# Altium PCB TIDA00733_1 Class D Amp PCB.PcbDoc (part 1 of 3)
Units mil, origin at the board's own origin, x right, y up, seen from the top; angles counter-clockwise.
Board outline 5700 x 4500 mil, 4 copper layers (Top Layer, Signal Layer 1, Signal Layer 2, Bottom Layer), stack 61.668 mil thick; 305 components, 186 nets, 894 pads, 1056 vias.
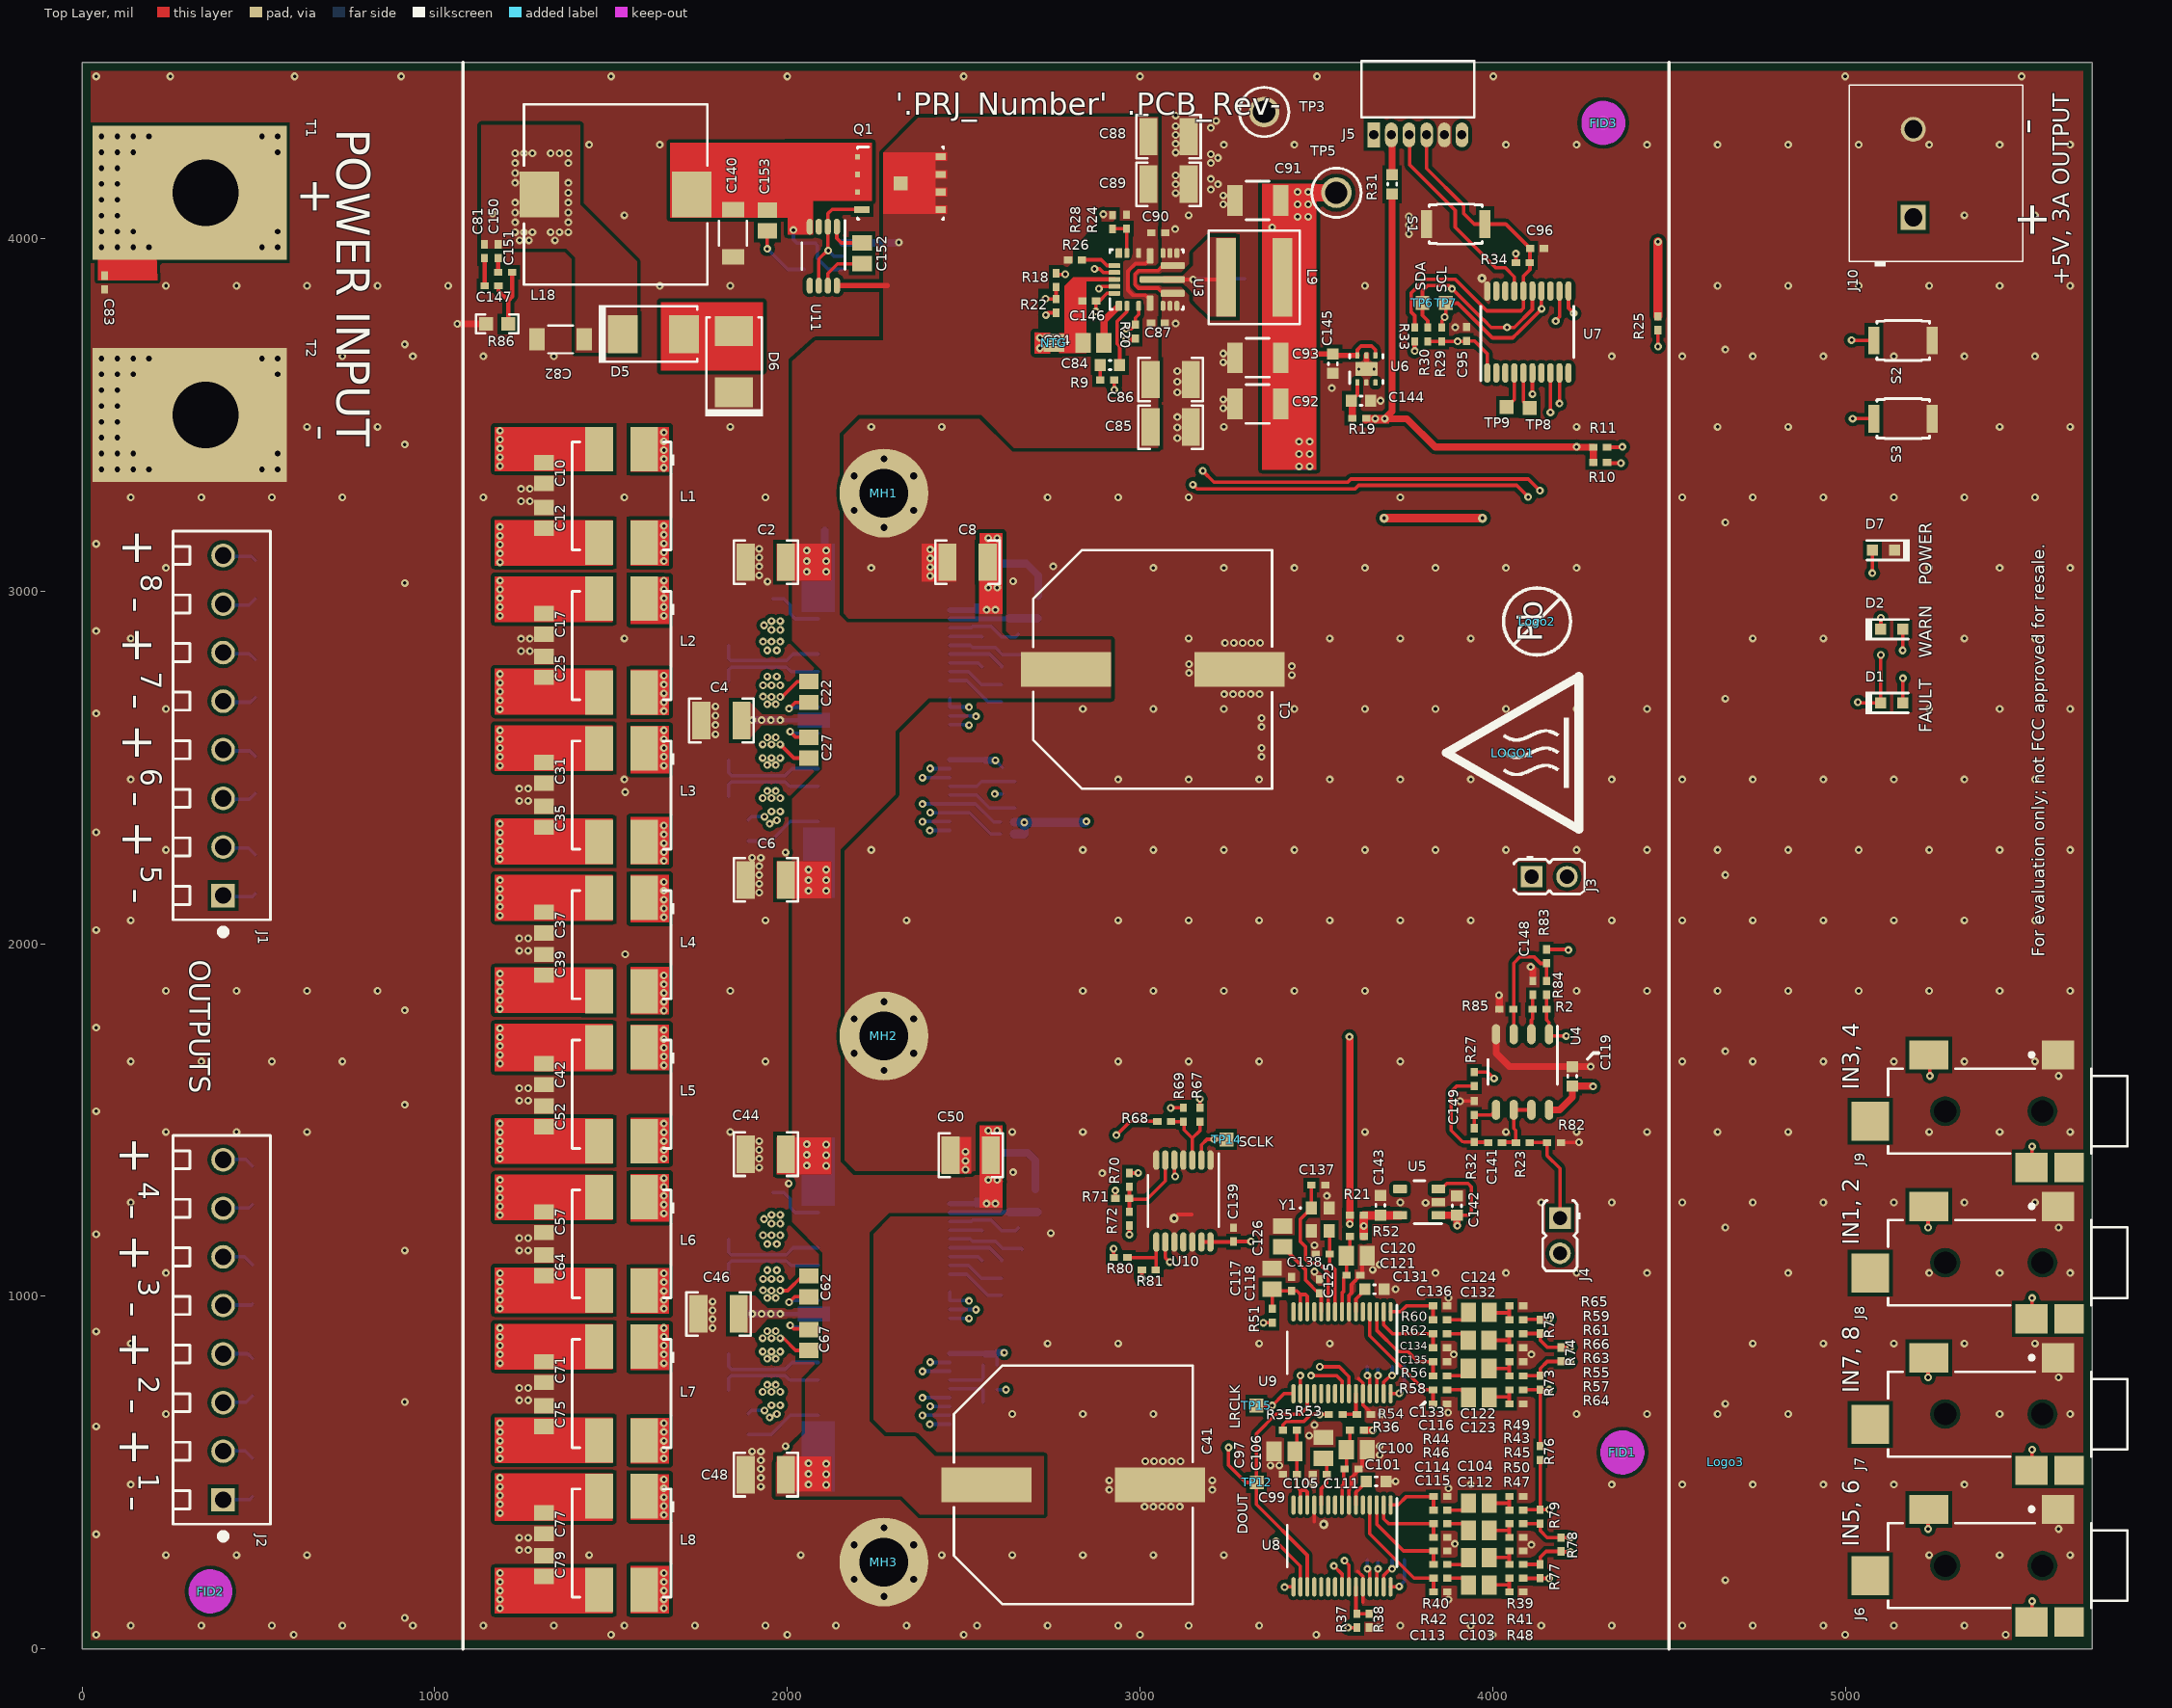
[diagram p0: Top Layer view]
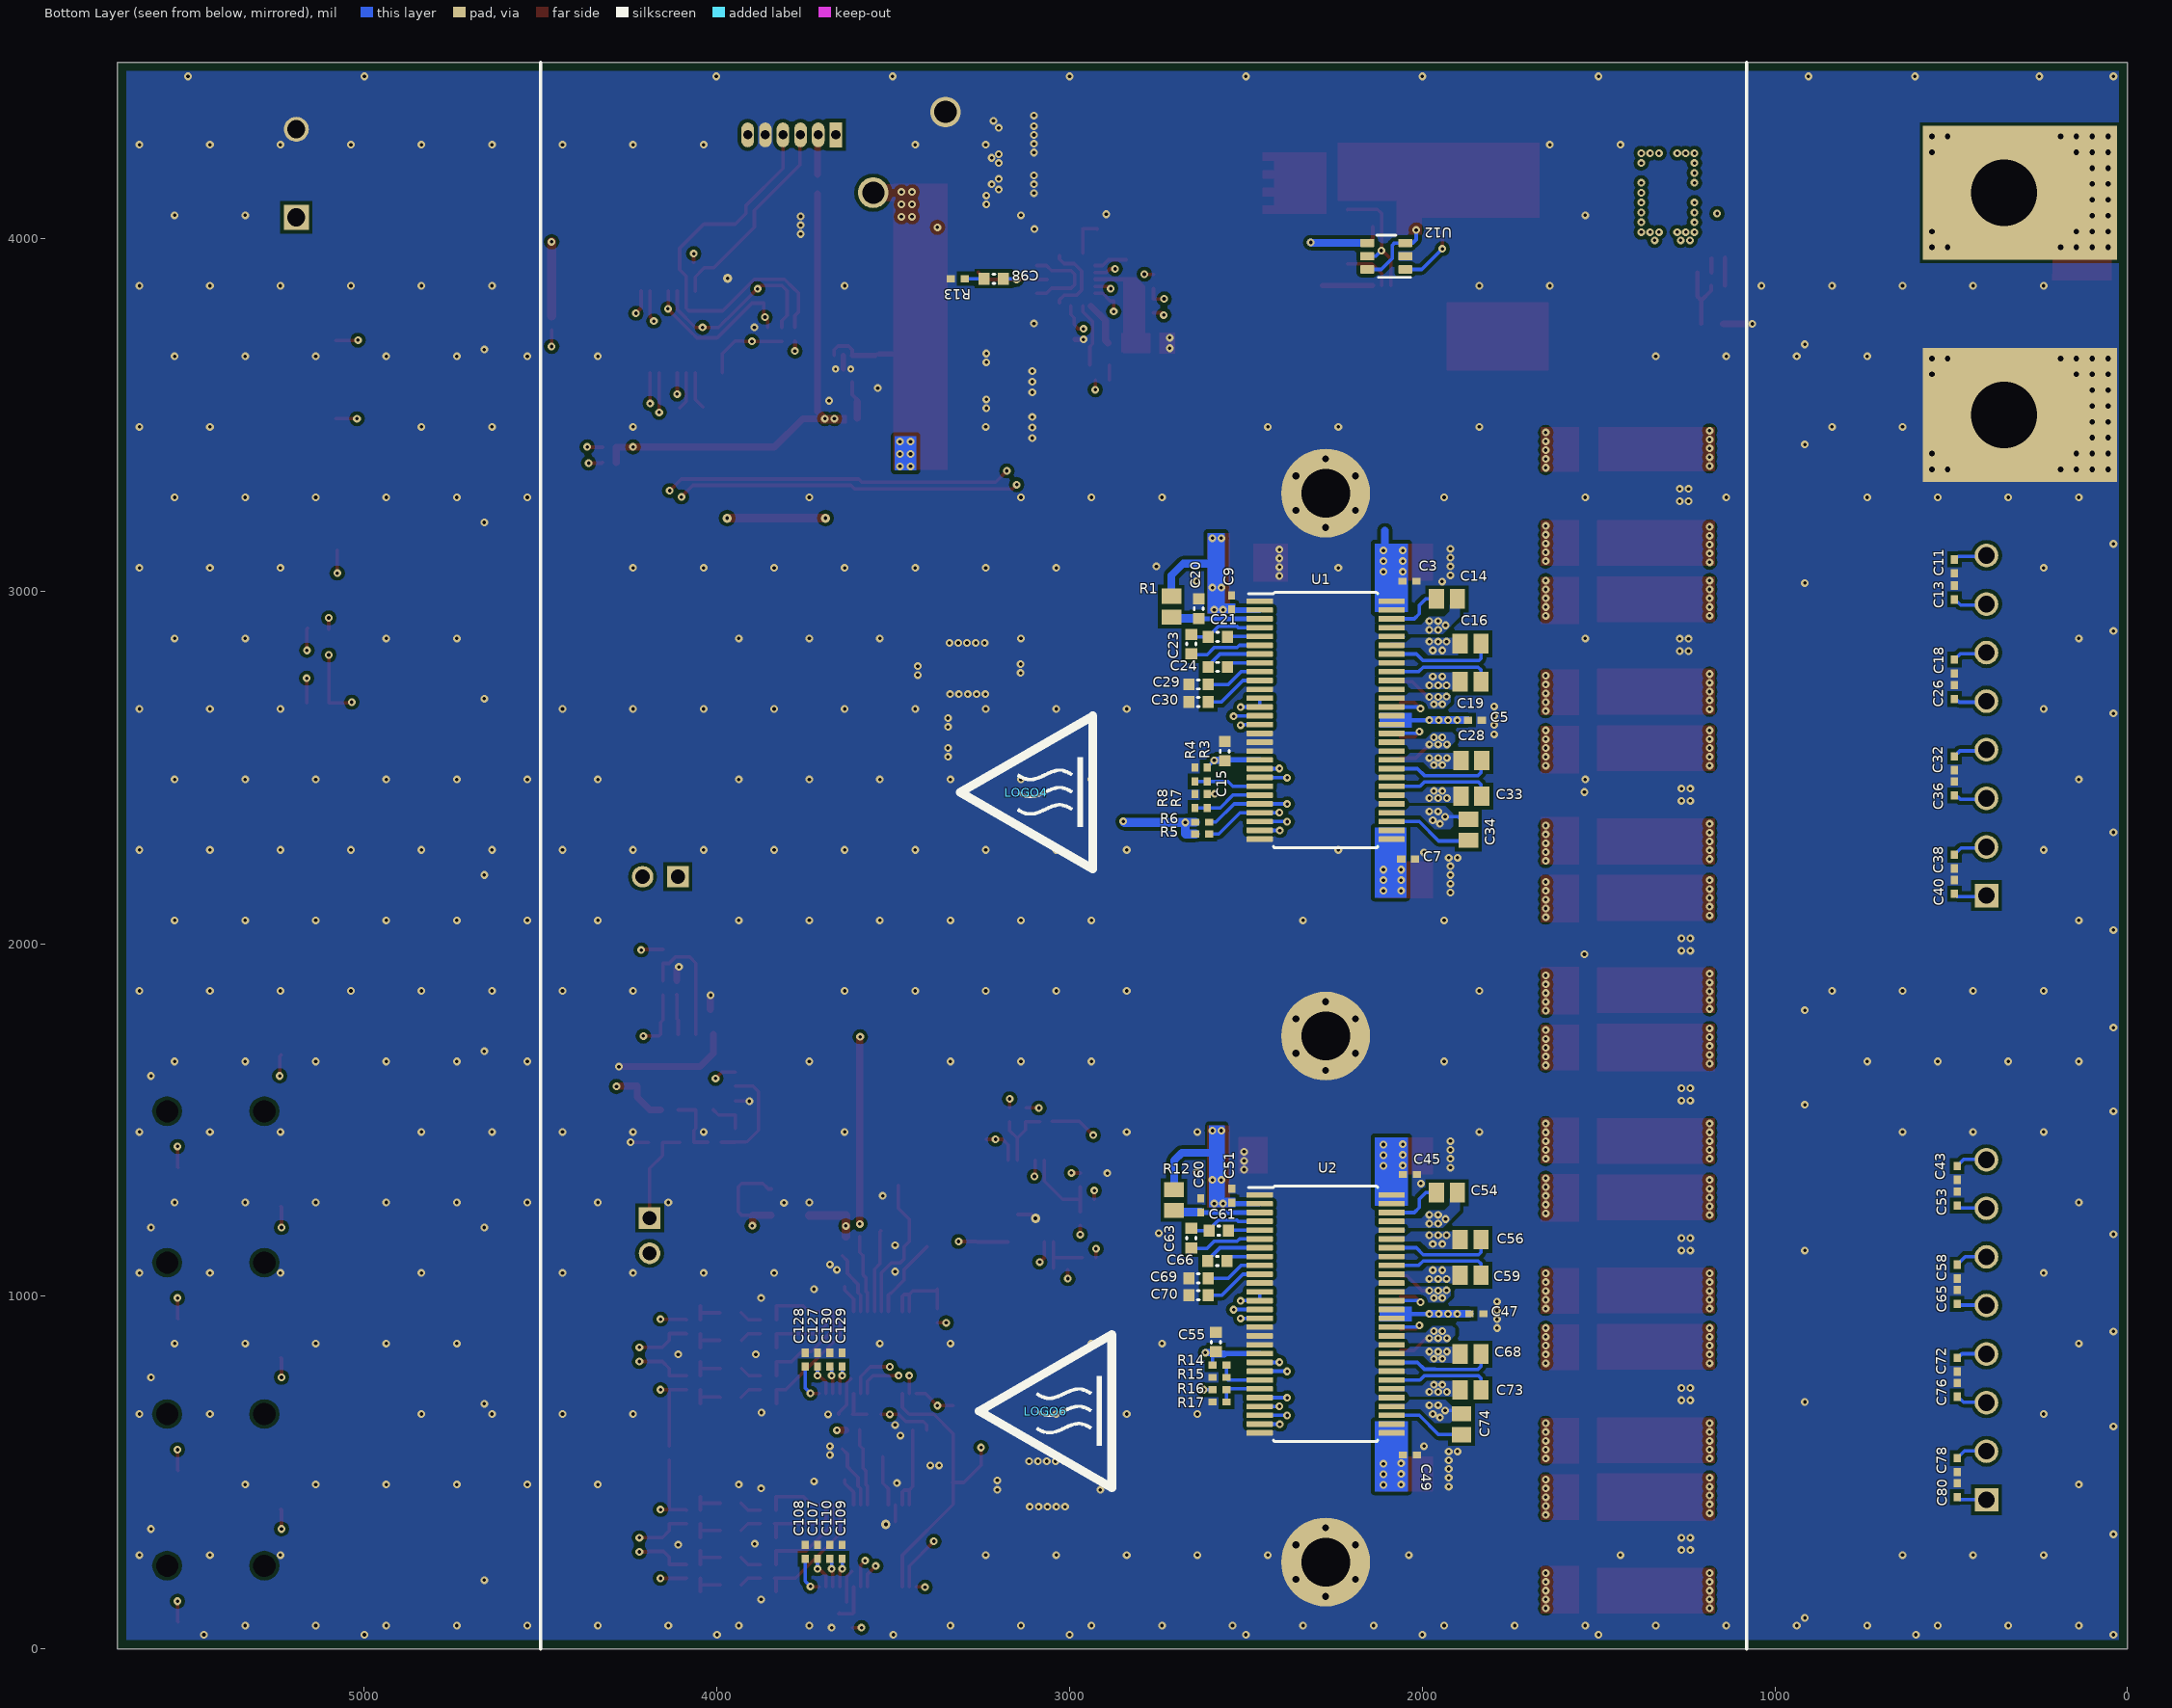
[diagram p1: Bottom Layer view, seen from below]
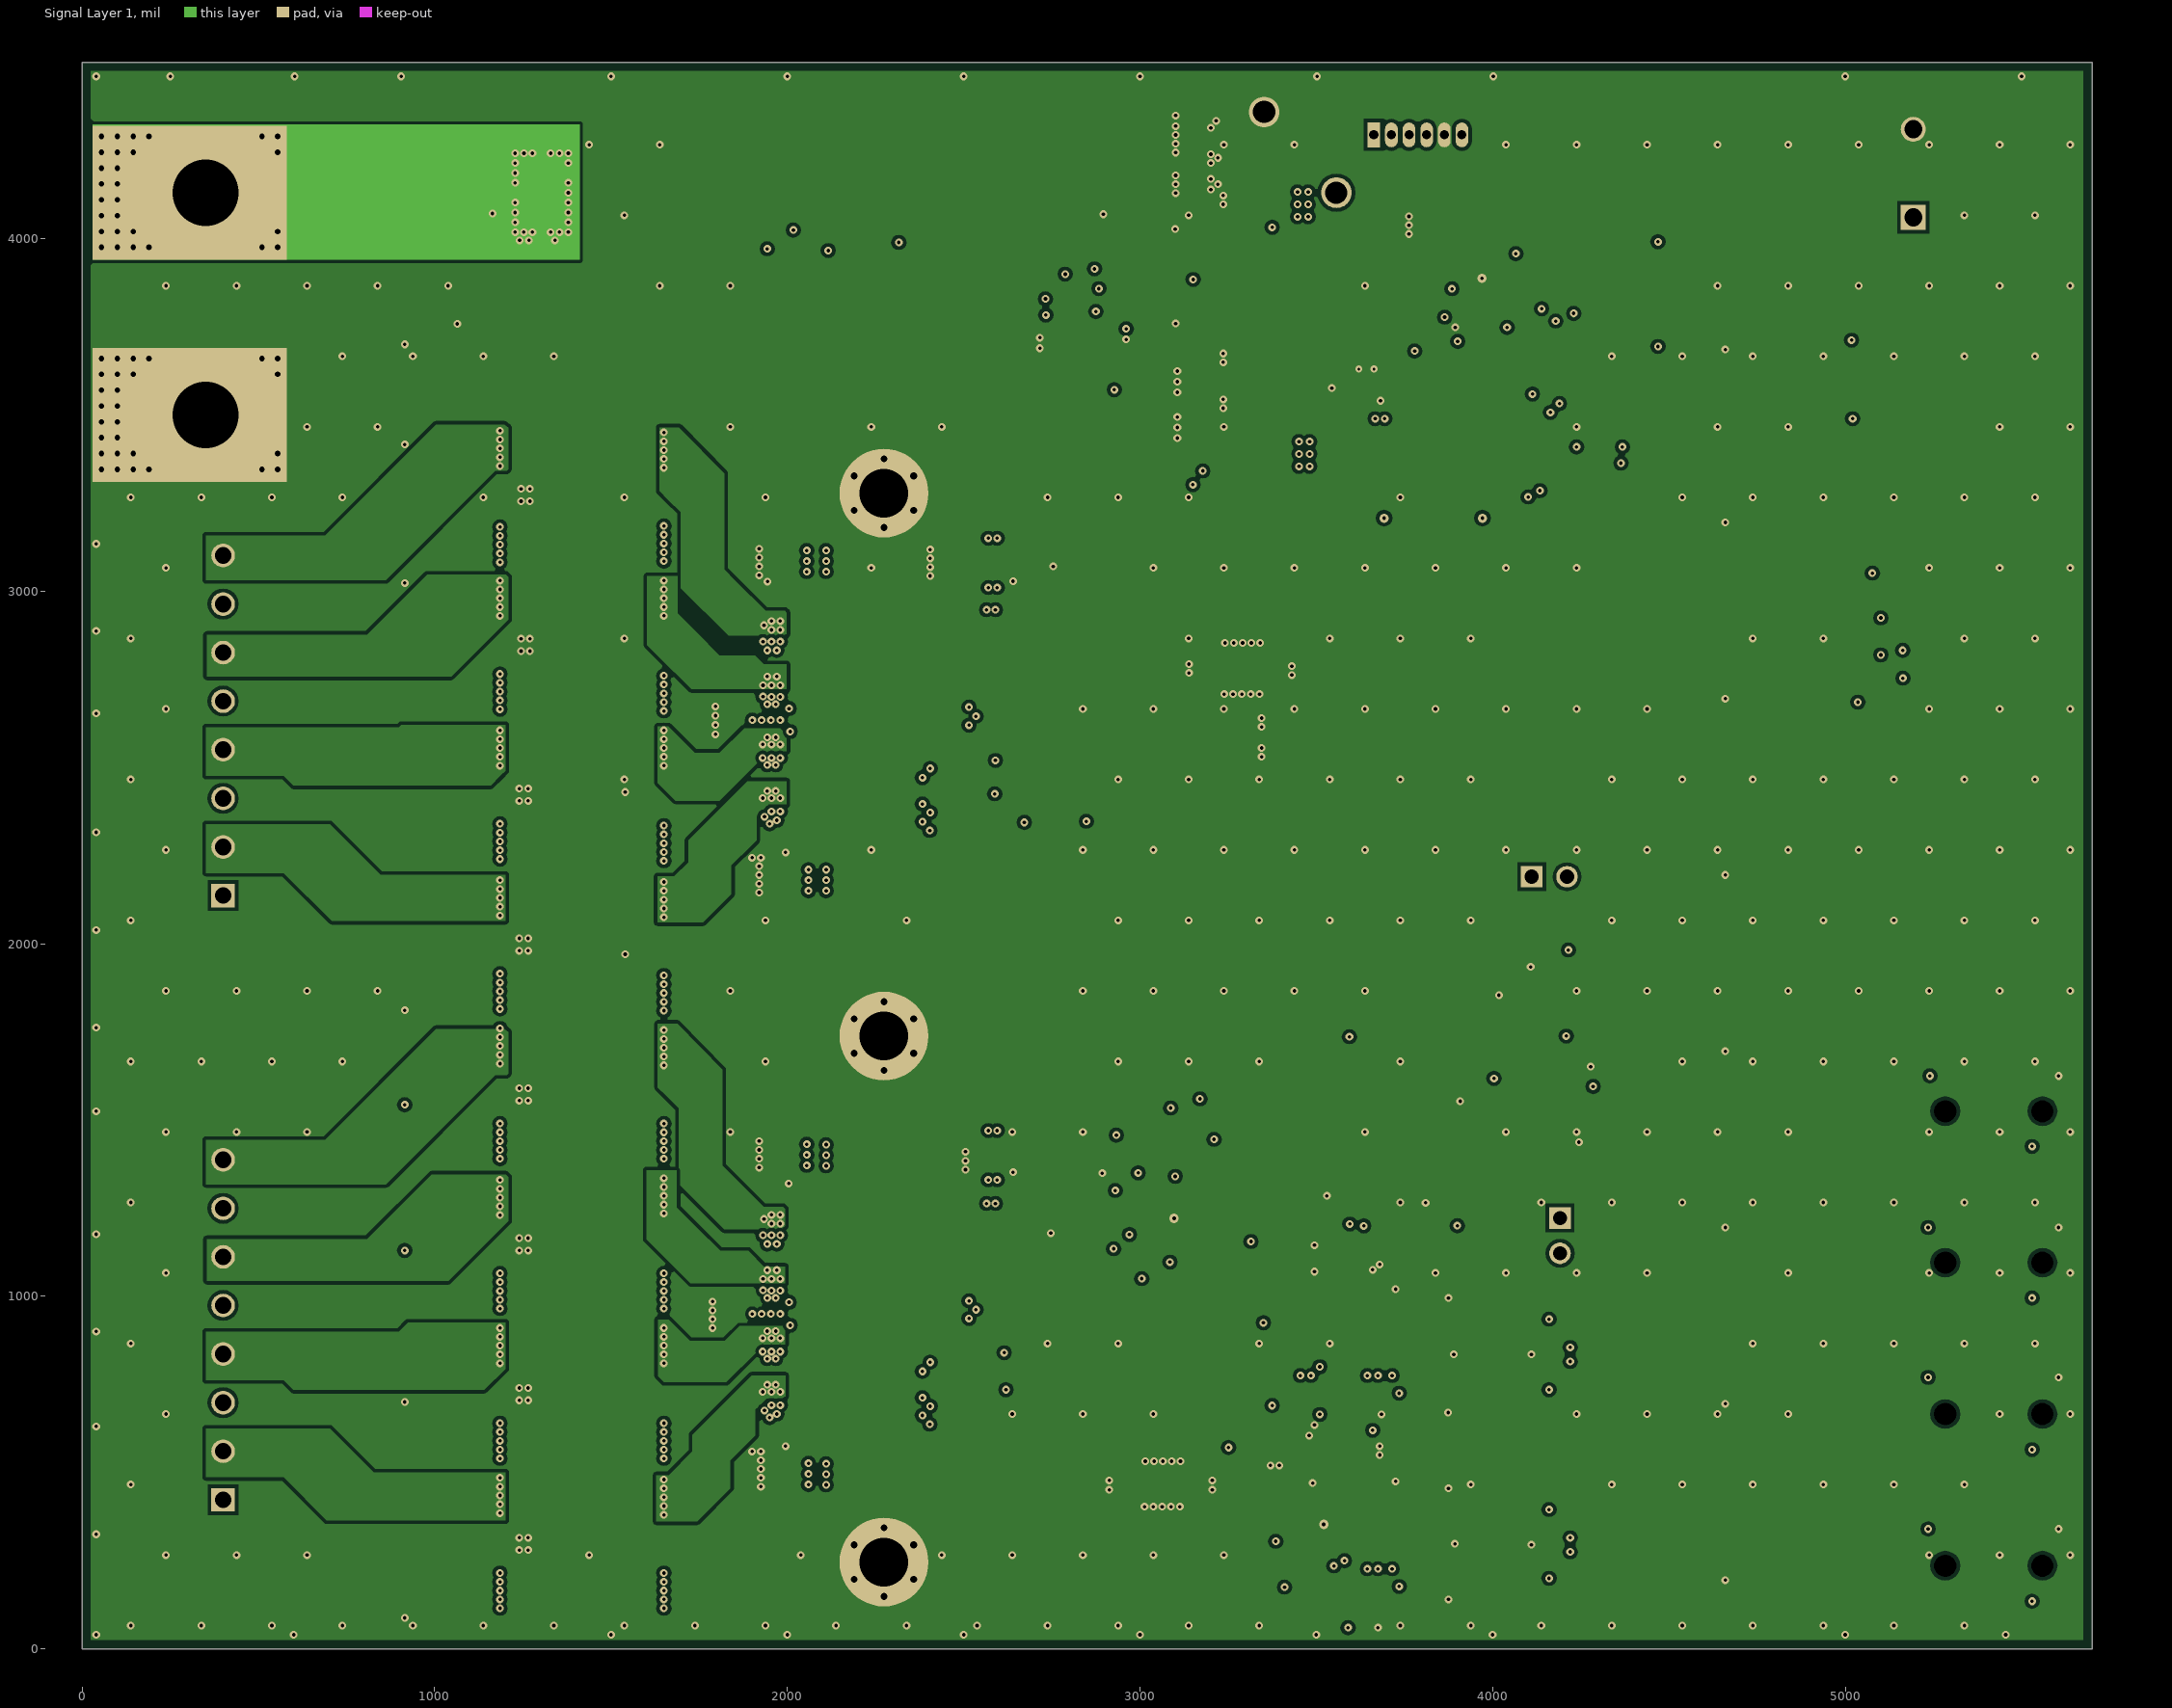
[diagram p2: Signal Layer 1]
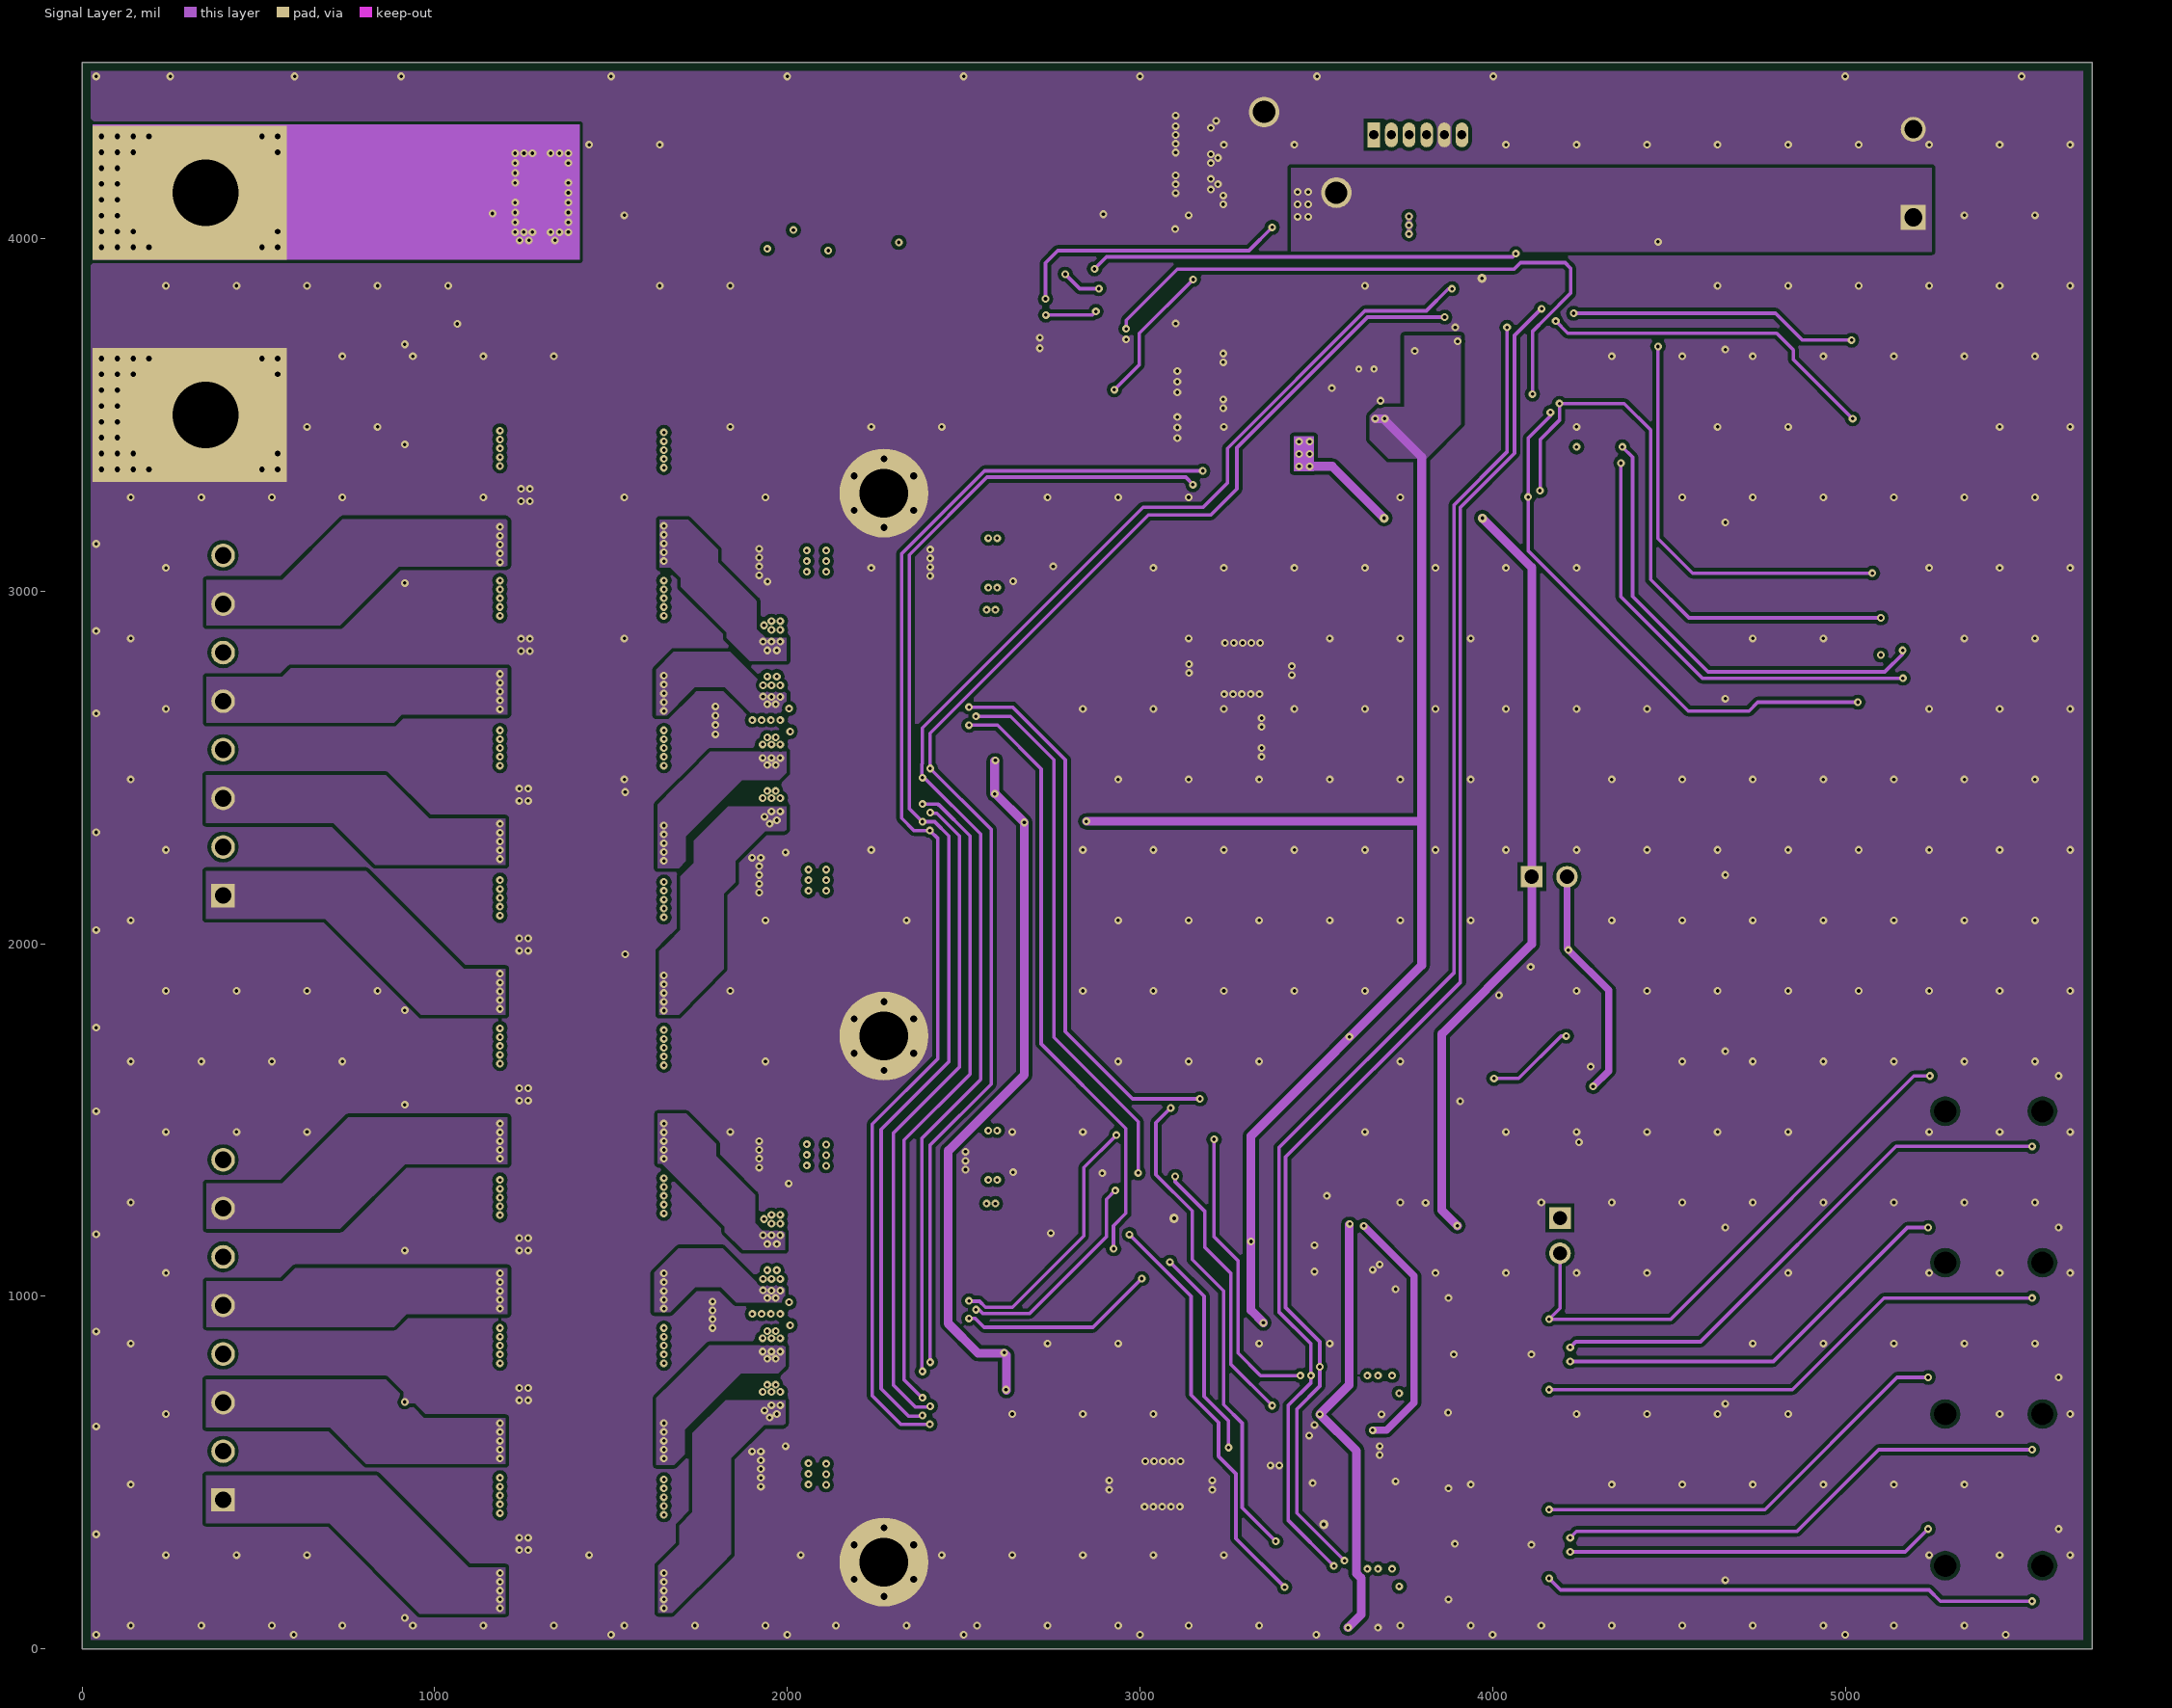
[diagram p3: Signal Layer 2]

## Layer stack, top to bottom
Top Solder: solder mask 0.4, Solder Resist, Dk 3.5
Top Layer: signal copper 1.417
Dielectric1: core 10, FR-4 High TG, Dk 4.3
Signal Layer 1: signal copper 1.417
Dielectric 2: prepreg 36, FR-4 High TG, Dk 4.2
Signal Layer 2: signal copper 1.417
Dielectric 3: core 10, FR-4 High TG, Dk 4.2
Bottom Layer: signal copper 1.417
Bottom Solder: solder mask 0.4, Solder Resist, Dk 3.5

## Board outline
0,0 0,4500 5700,4500 5700,0

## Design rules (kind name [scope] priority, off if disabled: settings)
AcuteAngle [All] p1: minimum=4.50000000000000E+0001 checktracksonly=FALSE
AssemblyTestPointUsage [All] p1: valid=2
BoardOutlineClearance BoardOutlineClearance_MountingHoles [OnCopper and InComponentClass('Mounting Holes')] p1: gap=40 ignorepadtopadclearanceinfootprint=FALSE
BoardOutlineClearance BoardOutlineClearance_Poly [OnCopper and InPoly] p2: gap=25 ignorepadtopadclearanceinfootprint=FALSE
BoardOutlineClearance [OnCopper and Not InComponentClass('Logo') and not InComponentClass('FiducialMark') and not InRegion(1000,500,4000,800)] p3: gap=25 ignorepadtopadclearanceinfootprint=FALSE
Clearance Clearance_1 [HasFootprint('RNL0022A_NV')] p1: gap=5.9 ignorepadtopadclearanceinfootprint=FALSE except(0: Arc-Hole Track-Hole SMDPad-Hole THPad-Hole Via-Hole Fill-Hole Poly-Hole Region-Hole Text-Hole)
Clearance Clearance_Keepouts [((IsTrack Or IsArc) And Not InPoly) And IsFree and IsKeepOut vs ((IsTrack Or IsArc) And Not InPoly) And IsFree and IsKeepOut] p2: gap=0 ignorepadtopadclearanceinfootprint=FALSE
Clearance Clearance_Poly [InPolygon] p3: gap=10 ignorepadtopadclearanceinfootprint=FALSE except(0: Arc-Hole Track-Hole SMDPad-Hole THPad-Hole Via-Hole Fill-Hole Poly-Hole Region-Hole Text-Hole)
Clearance [All] p4: gap=7.8 ignorepadtopadclearanceinfootprint=FALSE except(0: Arc-Hole Track-Hole SMDPad-Hole THPad-Hole Via-Hole Fill-Hole Poly-Hole Region-Hole Text-Hole)
ComponentClearance ComponentClearance_1 [HasGenericStepModel] p1: gap=0 collisioncheckmode=3 verticalgap=0 showdistances=FALSE
ComponentClearance ComponentClearance_MountingHoles_FiducialMarks [InComponentClass('Mounting Holes') vs InComponentClass('FiducialMark')] p2: gap=50 collisioncheckmode=3 verticalgap=10 showdistances=FALSE
ComponentClearance ComponentClearance_Shunt [InComponentClass('Header') vs InComponentClass('Shunt')] p3: gap=0 collisioncheckmode=3 verticalgap=0 showdistances=FALSE
ComponentClearance ComponentClearance_Logo [InComponentClass('Logo')] p4: gap=50 collisioncheckmode=3 verticalgap=10 showdistances=FALSE
ComponentClearance ComponentClearance_ScrewToNut [(HasFootprint('NY PMS 440 0025 PH')) vs (HasFootprint('Keystone_1902C'))] p5: gap=5 collisioncheckmode=3 verticalgap=10 showdistances=FALSE
ComponentClearance ComponentClearance_MountingHoles [InComponentClass('Mounting Holes')] p6: gap=250 collisioncheckmode=3 verticalgap=100000 showdistances=FALSE
ComponentClearance ComponentClearance_SmallPassives [HasFootprint('0201*') or HasFootprint('0402*') or HasFootprint('0508') or HasFootprint('0603*') or HasFootprint('0612') or HasFootprint('0805*') or HasFootprint('0815*') or HasFootprint('0830*') or HasFootprint('1206*') or HasFootprint('1210*') or HasFootprint('1808*') or HasFootprint('1812*') or HasFootprint('1825*') or HasFootprint('2010*') or HasFootprint('2220*') or HasFootprint('2225*') or HasFootprint('2512*') or HasFootprint('2728*') or HasFootprint('3518*') vs HasFootprint('0201*') or HasFootprint('0402*') or HasFootprint('0508') or HasFootprint('0603*') or HasFootprint('0612') or HasFootprint('0805*') or HasFootprint('0815*') or HasFootprint('0830*') or HasFootprint('1206*') or HasFootprint('1210*') or HasFootprint('1808*') or HasFootprint('1812*') or HasFootprint('1825*') or HasFootprint('2010*') or HasFootprint('2220*') or HasFootprint('2225*') or HasFootprint('2512*') or HasFootprint('2728*') or HasFootprint('3518*')] p7: gap=10 collisioncheckmode=3 verticalgap=10 showdistances=FALSE
ComponentClearance ComponentClearance_THtoSMT [IsThruComponent vs IsSMTComponent] p8: gap=30 collisioncheckmode=3 verticalgap=30 showdistances=FALSE
ComponentClearance ComponentClearance_THtoTH [IsThruComponent vs IsThruComponent] p9: gap=20 collisioncheckmode=3 verticalgap=20 showdistances=FALSE
ComponentClearance [All] p10: gap=20 collisioncheckmode=3 verticalgap=10 showdistances=FALSE
DiffPairsRouting [All] p1: maxlimit=100 minlimit=10 mostfreqgap=10 toplayer_minwidth=15 toplayer_maxwidth=15 toplayer_prefwidth=15 midlayer1_minwidth=15 midlayer1_maxwidth=15 midlayer1_prefwidth=15 midlayer2_minwidth=15 midlayer2_maxwidth=15 midlayer2_prefwidth=15 bottomlayer_minwidth=15 bottomlayer_maxwidth=15 bottomlayer_prefwidth=15 maxuncoupledlength=1000
FabricationTestPointUsage TestPointUsage [All] p1: valid=2 allowmultiple=FALSE
FabricationTestpoint Testpoint [All] p1: side=3 testpointundercomponent=TRUE minsize=40 maxsize=100 preferedsize=60 minholesize=0 maxholesize=40 preferedholesize=32 testpointgrid=1 allowsidetop=TRUE allowsidebottom=TRUE usegrid=TRUE gridtolerance=0.01
FanoutControl Fanout_LCC [IsLCC] p1: bgadir=Out bgaviamode=Centered fanoutstyle=Auto fanoutdirection=Alternating viagrid=1 // Fanout_LCC (Default Rule)
FanoutControl Fanout_BGA [IsBGA] p2: bgadir=Out bgaviamode=Centered fanoutstyle=Auto fanoutdirection=Alternating viagrid=1 // Fanout_BGA (Default Rule)
FanoutControl Fanout_Default [All] p4: bgadir=Out bgaviamode=Centered fanoutstyle=Auto fanoutdirection=Alternating viagrid=1 // Fanout_Default (Default Rule)
FanoutControl Fanout_Small [(CompPinCount < 5)] p5: bgadir=Out bgaviamode=Centered fanoutstyle=Auto fanoutdirection=OutThenIn viagrid=1 // Fanout_Small (Default Rule)
HoleSize [All] p1: absolutevalues=TRUE maxlimit=251 minlimit=7.87 maxpercent=80.000 minpercent=20.000
MinimumAnnularRing MinimumAnnularRing_1 [InComponent('J5')] p1: minimumring=4.99
MinimumAnnularRing MinimumAnnularRing_ThermalPadVias [IsVia and InAnyComponent] p2: minimumring=5.91
MinimumAnnularRing [All] p3: minimumring=6
MinimumSolderMaskSliver MinimumSolderMaskSliver_Logo [InComponentClass('Logo') vs InComponentClass('Logo')] p1: minsoldermaskwidth=0.7
MinimumSolderMaskSliver [All] p2: minsoldermaskwidth=3.94
PlaneConnect [All] p1: planeconnectstyle=Relief reliefexpansion=10 reliefentries=4 reliefconductorwidth=10 reliefairgap=10
PolygonConnect [All] p1: connectstyle=Direct reliefconductorwidth=10 reliefentries=4 polygonreliefangle="90 Angle" airgapwidth=10
RoutingVias ThermalPadVias [IsVia and InAnyComponent] p1: holewidth=7.87 width=19.68 viastyle="Through Hole" minholewidth=7.87 minwidth=19.68 maxholewidth=20 maxwidth=40
RoutingVias [All] p2: holewidth=10 width=26 viastyle="Through Hole" minholewidth=7.87 minwidth=22 maxholewidth=40 maxwidth=65
SilkToBoardRegionClearance [Not ((IsComment or IsDesignator) And (Hide <> 'False')) and not InRegion(1000,500,4000,800)] p1:
SilkToSilkClearance SilkToSilkClearance_Pb-FreeLogo [(HasFootprint('Pb-Free_Overlay_Medium') OR HasFootprint('Pb-Free_Overlay_Small')) vs (HasFootprint('Pb-Free_Overlay_Medium') OR HasFootprint('Pb-Free_Overlay_Small'))] p1: silktosilkclearance=0
SilkToSilkClearance [All] p2: silktosilkclearance=4
SilkToSolderMaskClearance SilkToComponentPadClearance [IsPad and InAnycomponent] p1: minsilkscreentomaskgap=5 clearancetoexposedcopper=TRUE
SilkToSolderMaskClearance "Silk to Solder Mask Opening" [All] p2: minsilkscreentomaskgap=4 clearancetoexposedcopper=FALSE
SolderMaskExpansion [All] p1: expansion=1.97
Width [All] p1: maxlimit=100 minlimit=7.8 preferedwidth=10 checkconnectedcopper=TRUE
15 further rules are at their usual default settings.

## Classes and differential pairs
component class Shunt: SH-J1 SH-J2
component class Header: J3 J4
component class FiducialMark: FID1 FID2 FID3
component class AssemblyNote: ZZ1
component class "TIDA00733_1 Class D Amp Sheet 6": C117 C118 C120 C121 C122 C123 C124 C125 C126 C127 C128 C129 C130 C131 C132 C133 C134 C135 C136 C137 C138 C139 J8 J9 R51 R52 R53 R54 R55 R56 R57 R58 R59 R60 R61 R62 R63 R64 R65 R66 R67 R68 R69 R70 R71 R72 R80 R81 TP12 TP14 TP15 U9 U10 Y1

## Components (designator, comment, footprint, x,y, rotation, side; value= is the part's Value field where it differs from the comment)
C1 "EEV-FK1H102M" SM_RADIAL_J16 3036,2778 r0 top value=1000uF
C2 "GRM32ER71H106KA12L" 1210_270 1939,3082 r180 top value=10uF
C3 "C1005X7R1H104K050BB" 0402L 2036,3028 r180 bottom value=0.1uF
C4 "GRM32ER71H106KA12L" 1210_270 1813,2633 r180 top value=10uF
C5 "C1005X7R1H104K050BB" 0402L 1851,2634 r180 bottom value=0.1uF
C6 "GRM32ER71H106KA12L" 1210_270 1939,2181 r180 top value=10uF
C7 "C1005X7R1H104K050BB" 0402L 2040,2240 r180 bottom value=0.1uF
C8 "GRM32ER71H106KA12L" 1210_270 2511,3082 r180 top value=10uF
C9 "C1005X7R1H104K050BB" 0402L 2541,2968 r90 bottom value=0.1uF
C10 "GRM21BR71H105KA12L" 0805L#1 1310,3335 r270 top value=1uF
C11 "GCM155R71H103KA55D" 0402L 491,3070 r270 bottom value=0.01uF
C12 "GRM21BR71H105KA12L" 0805L#1 1310,3208 r90 top value=1uF
C13 "GCM155R71H103KA55D" 0402L 491,2996 r90 bottom value=0.01uF
C14 "C2012X7R1H225K125AC" 0805L#1 1930,2978 r0 bottom value=2.2uF
C15 "C1608X7R1E105K080AB" 0603L 2560,2546 r90 bottom value=1uF
C16 "C2012X7R1H225K125AC" 0805L#1 1863,2851 r180 bottom value=2.2uF
C17 "GRM21BR71H105KA12L" 0805L#1 1310,2907 r270 top value=1uF
C18 "GCM155R71H103KA55D" 0402L 491,2786 r270 bottom value=0.01uF
C19 "C2012X7R1H225K125AC" 0805L#1 1863,2743 r180 bottom value=2.2uF
C20 "C1608X7R1E105K080AB" 0603L 2634,2950 r90 bottom value=1uF
C21 "C1608X7R1E105K080AB" 0603L 2580,2870 r0 bottom value=1uF
C22 "C2012X7R1H225K125AC" 0805L#1 2061,2714 r270 top value=2.2uF
C23 "C1608X7R1E105K080AB" 0603L 2655,2850 r90 bottom value=1uF
C24 "C1608X7R1E105K080AB" 0603L 2580,2785 r0 bottom value=1uF
C25 "GRM21BR71H105KA12L" 0805L#1 1310,2785 r90 top value=1uF
C26 "GCM155R71H103KA55D" 0402L 491,2714 r90 bottom value=0.01uF
C27 "C2012X7R1H225K125AC" 0805L#1 2061,2556 r90 top value=2.2uF
C28 "C2012X7R1H225K125AC" 0805L#1 1861,2520 r180 bottom value=2.2uF
C29 "C1608X7R1E105K080AB" 0603L 2634.81,2735.41 r0 bottom value=1uF
C30 "C1608X7R1E105K080AB" 0603L 2634.81,2685.41 r0 bottom value=1uF
C31 "GRM21BR71H105KA12L" 0805L#1 1310,2485 r270 top value=1uF
C32 "GCM155R71H103KA55D" 0402L 491,2512 r270 bottom value=0.01uF
C33 "C2012X7R1H225K125AC" 0805L#1 1861,2418 r180 bottom value=2.2uF
C34 "C2012X7R1H225K125AC" 0805L#1 1869,2323 r270 bottom value=2.2uF
C35 "GRM21BR71H105KA12L" 0805L#1 1310,2360 r90 top value=1uF
C36 "GCM155R71H103KA55D" 0402L 491,2440 r90 bottom value=0.01uF
C37 "GRM21BR71H105KA12L" 0805L#1 1310,2060 r270 top value=1uF
C38 "GCM155R71H103KA55D" 0402L 491,2233 r270 bottom value=0.01uF
C39 "GRM21BR71H105KA12L" 0805L#1 1310,1940 r90 top value=1uF
C40 "GCM155R71H103KA55D" 0402L 491,2161 r90 bottom value=0.01uF
C41 "EEV-FK1H102M" SM_RADIAL_J16 2811,465 r0 top value=1000uF
C42 "GRM21BR71H105KA12L" 0805L#1 1310,1630 r270 top value=1uF
C43 "GCM155R71H103KA55D" 0402L 483,1350 r270 bottom value=0.01uF
C44 "GRM32ER71H106KA12L" 1210_270 1939,1403 r180 top value=10uF
C45 "C1005X7R1H104K050BB" 0402L 2035,1345 r180 bottom value=0.1uF
C46 "GRM32ER71H106KA12L" 1210_270 1805,950 r180 top value=10uF
C47 "C1005X7R1H104K050BB" 0402L 1846,950 r180 bottom value=0.1uF
C48 "GRM32ER71H106KA12L" 1210_270 1939,494 r180 top value=10uF
C49 "C1005X7R1H104K050BB" 0402L 2035,550 r180 bottom value=0.1uF
C50 "GRM32ER71H106KA12L" 1210_270 2520,1400 r180 top value=10uF
C51 "C1005X7R1H104K050BB" 0402L 2540,1285 r90 bottom value=0.1uF
C52 "GRM21BR71H105KA12L" 0805L#1 1310,1510 r90 top value=1uF
C53 "GCM155R71H103KA55D" 0402L 483,1277 r90 bottom value=0.01uF
C54 "C2012X7R1H225K125AC" 0805L#1 1930,1294 r0 bottom value=2.2uF
C55 "C1608X7R1E105K080AB" 0603L 2585,870 r90 bottom value=1uF
C56 "C2012X7R1H225K125AC" 0805L#1 1863,1161 r180 bottom value=2.2uF
C57 "GRM21BR71H105KA12L" 0805L#1 1310,1210 r270 top value=1uF
C58 "GCM155R71H103KA55D" 0402L 483,1070 r270 bottom value=0.01uF
C59 "C2012X7R1H225K125AC" 0805L#1 1863,1060 r180 bottom value=2.2uF
C60 "C1005X7R1H104K050BB" 0402L 2628,1258 r90 bottom value=0.1uF
C61 "C1608X7R1E105K080AB" 0603L 2577,1186 r0 bottom value=1uF
C62 "C2012X7R1H225K125AC" 0805L#1 2061,1028 r270 top value=2.2uF
C63 "C1608X7R1E105K080AB" 0603L 2655,1165 r90 bottom value=1uF
C64 "GRM21BR71H105KA12L" 0805L#1 1310,1088 r90 top value=1uF
C65 "GCM155R71H103KA55D" 0402L 483,998 r90 bottom value=0.01uF
C66 "C1608X7R1E105K080AB" 0603L 2581,1100 r0 bottom value=1uF
C67 "C2012X7R1H225K125AC" 0805L#1 2061,876 r90 top value=2.2uF
C68 "C2012X7R1H225K125AC" 0805L#1 1863,836 r180 bottom value=2.2uF
C69 "C1608X7R1E105K080AB" 0603L 2634.81,1050.81 r0 bottom value=1uF
C70 "C1608X7R1E105K080AB" 0603L 2634.81,1002.81 r0 bottom value=1uF
C71 "GRM21BR71H105KA12L" 0805L#1 1310,785 r270 top value=1uF
C72 "GCM155R71H103KA55D" 0402L 483,806 r270 bottom value=0.01uF
C73 "C2012X7R1H225K125AC" 0805L#1 1863,734 r180 bottom value=2.2uF
C74 "C2012X7R1H225K125AC" 0805L#2 1889,637 r180 bottom value=2.2uF
C75 "GRM21BR71H105KA12L" 0805L#1 1310,660 r90 top value=1uF
C76 "GCM155R71H103KA55D" 0402L 483,735 r90 bottom value=0.01uF
C77 "GRM21BR71H105KA12L" 0805L#1 1310,356 r270 top value=1uF
C78 "GCM155R71H103KA55D" 0402L 483,521 r270 bottom value=0.01uF
C79 "GRM21BR71H105KA12L" 0805L#1 1310,235 r90 top value=1uF
C80 "GCM155R71H103KA55D" 0402L 483,450 r90 bottom value=0.01uF
C81 "C1005X7R1H104K050BB" 0402L 1141,3964 r270 top value=0.1uF
C82 "GRM31CR71H475KA12L" 1206_180 1357,3714 r180 top value=4.7uF
C83 "C1005X7R1H104K050BB" 0402L 64,3875 r270 top value=0.1uF
C84 "GRM188R71E474KA12D" 0603L 2915,3641 r0 top value=0.47uF
C85 "GRM32ER71H106KA12L" 1210_270 3087,3465 r0 top value=10uF
C86 "GRM32ER71H106KA12L" 1210_270 3087,3600 r0 top value=10uF
C87 "C1005X7R1H104K050BB" 0402L 3051,3761 r0 top value=0.1uF
C88 "GRM32ER71H106KA12L" 1210_270 3081,4289 r0 top value=10uF
C89 "GRM32ER71H106KA12L" 1210_270 3081,4154 r0 top value=10uF
C90 "C1005X7R1H104K050BB" 0402L 3052,4016 r0 top value=0.1uF
C91 "CGA6P1X7R1C226M250AC" 1210_280 3334,4108 r180 top value=22uF
C92 "CGA6P1X7R1C226M250AC" 1210_280 3334,3531 r180 top value=22uF
C93 "CGA6P1X7R1C226M250AC" 1210_280 3334,3662 r180 top value=22uF
C94 "GRM21BR71A475KA73L" 0805L#1 2868,3704 r180 top value=4.7uF
C95 "C1005X7R1H104K050BB" 0402L 3926,3729 r90 top value=0.1uF
C96 "GRM155R71H222KA01D" 0402L 4126,3972 r0 top value=2200pF
C97 "GRM21BR71A106KE51L" 0805L#1 3410,560 r180 top value=10uF
C98 "06035A102KAT2A" 0603L 3215,3886 r0 bottom value=1000pF
C99 "C1005X7R1H104K050BB" 0402L 3425,495 r180 top value=0.1uF
C100 "GRM21BR71A106KE51L" 0805L#1 3615,565 r0 top value=10uF
C101 "C1005X7R1H104K050BB" 0402L 3600,510 r0 top value=0.1uF
C102 "GRM21BR71A106KE51L" 0805L#1 3961,259 r0 top value=10uF
C103 "GRM21BR71A106KE51L" 0805L#1 3961,181 r0 top value=10uF
C104 "GRM21BR71A106KE51L" 0805L#1 3961,413 r0 top value=10uF
C105 "C1005X7R1H104K050BB" 0402L 3510,495 r180 top value=0.1uF
C106 "GRM21BR71H105KA12L" 0805L#1 3520,570 r90 top value=1uF
C107 "C1005X7R1H104K050BB" 0402L 3715,275 r90 bottom value=0.1uF
C108 "C1005X7R1H104K050BB" 0402L 3750,275 r90 bottom value=0.1uF
C109 "C1005X7R1H104K050BB" 0402L 3645,275 r90 bottom value=0.1uF
C110 "C1005X7R1H104K050BB" 0402L 3680,275 r90 bottom value=0.1uF
C111 "GCM188R70J225KE22D" 0603L 3670,475 r0 top value=2.2uF
C112 "GRM21BR71A106KE51L" 0805L#1 3961,336 r0 top value=10uF
C113 "885012205031" 0402L 3852,162 r0 top value=0.01uF
C114 "885012205031" 0402L 3852,316.29 r0 top value=0.01uF
C115 "885012205031" 0402L 3852,277.71 r0 top value=0.01uF
C116 "885012205031" 0402L 3852,432 r0 top value=0.01uF
C117 "GRM21BR71A106KE51L" 0805L#1 3375,1050 r90 top value=10uF
C118 "C1005X7R1H104K050BB" 0402L 3430,1035 r90 top value=0.1uF
C119 "C1608X7R1E105K080AB" 0603L 4226,1624 r90 top value=1uF
C120 "GRM21BR71A106KE51L" 0805L#1 3615,1115 r0 top value=10uF
C121 "C1005X7R1H104K050BB" 0402L 3605,1060 r0 top value=0.1uF
C122 "GRM21BR71A106KE51L" 0805L#1 3960,795 r180 top value=10uF
C123 "GRM21BR71A106KE51L" 0805L#1 3961,713 r180 top value=10uF
C124 "GRM21BR71A106KE51L" 0805L#1 3961,954 r180 top value=10uF
C125 "C1005X7R1H104K050BB" 0402L 3509,1028 r90 top value=0.1uF
C126 "GRM21BR71H105KA12L" 0805L#1 3405,1170 r90 top value=1uF
C127 "C1005X7R1H104K050BB" 0402L 3715,820 r90 bottom value=0.1uF
C128 "C1005X7R1H104K050BB" 0402L 3750,820 r90 bottom value=0.1uF
C129 "C1005X7R1H104K050BB" 0402L 3645,820 r90 bottom value=0.1uF
C130 "C1005X7R1H104K050BB" 0402L 3680,820 r90 bottom value=0.1uF
C131 "GCM188R70J225KE22D" 0603L 3665,1020 r0 top value=2.2uF
C132 "GRM21BR71A106KE51L" 0805L#1 3960,875 r180 top value=10uF
C133 "885012205031" 0402L 3851,695 r0 top value=0.01uF
C134 "885012205031" 0402L 3851,853.86 r0 top value=0.01uF
C135 "885012205031" 0402L 3851,814.14 r0 top value=0.01uF
C136 "885012205031" 0402L 3851,973 r0 top value=0.01uF
C137 "GRM1555C1H200JA01D" 0402L 3506,1315 r0 top value=20pF
C138 "GRM1555C1H200JA01D" 0402L 3518,1120 r180 top value=20pF
C139 "C1005X7R1H104K050BB" 0402L 3265,1175 r90 top value=0.1uF
C140 "GRM31CR71H475KA12L" 1206_180 1846,4015 r270 top value=4.7uF
C141 "GRM155R71H223KA12D" 0402L 4007,1436 r180 top value=0.022uF
C142 "C1608X7R1E105K080AB" 0603L 3899,1257 r90 top value=1uF
C143 "C1608X7R1E105K080AB" 0603L 3682,1258 r90 top value=1uF
C144 "C1608X7R1E105K080AB" 0603L 3627,3540 r0 top value=1uF
C145 "C1608X7R1E105K080AB" 0603L 3547,3645 r270 top value=1uF
C146 "C1005X7R1H104K050BB" 0402L 2856,3823 r180 top value=0.1uF
C147 "C1005X7R1H104K050BB" 0402L 1161,3866 r0 top value=0.1uF
C148 "GCM155R71H103KA55D" 0402L 4114,1875 r90 top value=0.01uF
C149 "GCM155R71H103KA55D" 0402L 3948,1534 r90 top value=0.01uF
C150 "C1005X7R1H104K050BB" 0402L 1180,3964 r270 top value=0.1uF
C151 "C1005X7R1H104K050BB" 0402L 1200,3904 r0 top value=0.1uF
C152 "C2012X7R1H225K125AC" 0805L#1 2212,3958 r90 top value=2.2uF
C153 "C2012X7R1H225K125AC" 0805L#1 1943,4051 r270 top value=2.2uF
D1 "150060SS75000" WL-SMCW_RED 5132,2683 r0 top value="Super Red"
D2 "150060YS75000" WL-SMCW_YELLOW 5132,2892 r0 top value=Yellow
D5 "SMBJ17A-13-F" SMB 1620,3729 r0 top value=17V
D6 "SMBJ14A-13-F" SMB 1849,3651 r90 top value=14V
D7 "150060VS75000" WL-SMCW_GREEN 5108.38,3116 r180 top value=Green
FID1 "Fiducial" Fiducial10-30 4368,557 r0 top
FID2 "Fiducial" Fiducial10-30 364,163 r0 top
FID3 "Fiducial" Fiducial10-30 4314,4328 r0 top
J1 "OSTTE080161" On-Shore_OSTTE080161 400,2619 r90 top
J2 "OSTTE080161" On-Shore_OSTTE080161 400,905 r90 top
J3 "0022284023" Molex_0022284023 4161,2190 r0 top
J4 "0022284023" Molex_0022284023 4191,1172 r270 top
J5 "851-43-006-20-001000" CONN_851-43-006-20-001000 3788,4294 r180 top
J6 "35RASMT4BHNTRX" Switchcraft_35RASM 5461,236 r270 top
J7 "35RASMT4BHNTRX" Switchcraft_35RASM 5461,665.67 r270 top
J8 "35RASMT4BHNTRX" Switchcraft_35RASM 5461,1095.33 r270 top
J9 "35RASMT4BHNTRX" Switchcraft_35RASM 5461,1525 r270 top
J10 "1714955" Phoenix_1714955 5193,4185 r90 top
L1 "VAMV06077E-3R3MM2" Cyntec_VAMV06077E 1530,3270 r270 top value=3.3uH
L2 "VAMV06077E-3R3MM2" Cyntec_VAMV06077E 1530,2845.71 r270 top value=3.3uH
L3 "VAMV06077E-3R3MM2" Cyntec_VAMV06077E 1530,2421.43 r270 top value=3.3uH
L4 "VAMV06077E-3R3MM2" Cyntec_VAMV06077E 1530,1997.14 r270 top value=3.3uH
L5 "VAMV06077E-3R3MM2" Cyntec_VAMV06077E 1530,1572.86 r270 top value=3.3uH
L6 "VAMV06077E-3R3MM2" Cyntec_VAMV06077E 1530,1148.57 r270 top value=3.3uH
L7 "VAMV06077E-3R3MM2" Cyntec_VAMV06077E 1530,724.29 r270 top value=3.3uH
L8 "VAMV06077E-3R3MM2" Cyntec_VAMV06077E 1530,300 r270 top value=3.3uH
L9 "XAL6030-222MEB" XAL6030 3324,3890 r0 top value=2.2uH
L18 "IHLP5050CEERR47M01" IHLP-5050CE 1513,4125 r0 top value=470nH
LOGO1 "CAUTION HOT SURFACE" IEC_HotSurface_Medium 4057,2541 r90 top
Logo2 "Pb-Free Symbol" Pb-Free_Overlay_Medium 4126,2914 r90 top
Logo3 "FCC disclaimer" FCC_disclaimer 4660,530 r90 top
LOGO4 "CAUTION HOT SURFACE" IEC_HotSurface_Medium 3122,2429 r90 bottom
LOGO6 "CAUTION HOT SURFACE" IEC_HotSurface_Medium 3068,674 r90 bottom
MH1 "MTG_Pads" MTGP_4-40_PanHead 2274,3278 r0 top
MH2 "MTG_Pads" MTGP_4-40_PanHead 2274,1738 r0 top
MH3 "MTG_Pads" MTGP_4-40_PanHead 2274,246 r0 top
NTG "Net-Tie" Net-Tie_50milWide_30milLong 2756,3704 r180 top net-tie
Q1 "BSC014N04LSI" TDSON-8_FL 2321,4157 r0 top value=40V
R1 "CRCW08050000Z0EA" 0805L#1 2711,2956 r270 bottom value=0
R2 "CRCW040271K5FKED" 0402L 4133,1814 r0 top value=71.5k
R3 "CRCW04024K99FKED" 0402L 2610,2480 r270 bottom value=4.99k
R4 "CRCW0402100KFKED" 0402L 2645,2480 r90 bottom value=100k
R5 "CRCW040210K0FKED" 0402L 2624,2311 r0 bottom value=10.0k
R6 "CRCW040210K0FKED" 0402L 2624,2345 r0 bottom value=10.0k
R7 "CRCW0402100KFKED" 0402L 2610,2405 r270 bottom value=100k
R8 "CRCW04024K99FKED" 0402L 2645,2405 r90 bottom value=4.99k
R9 "CRCW04023R00JNED" 0402L 2907,3599 r0 top value=3.0
R10 "CRCW04021K00FKED" 0402L 4305,3365 r0 top value=1.00k
R11 "CRCW04021K00FKED" 0402L 4305,3408 r0 top value=1.00k
R12 "CRCW08050000Z0EA" 0805L#1 2704,1273 r270 bottom value=0
R13 "CRCW04028R06FKED" 0402L 3317,3886 r180 bottom value=8.06
R14 "CRCW0402100KFKED" 0402L 2575,805 r180 bottom value=100k
R15 "CRCW04024K99FKED" 0402L 2575,770 r0 bottom value=4.99k
R16 "CRCW0402100KFKED" 0402L 2575,735 r180 bottom value=100k
R17 "CRCW04024K99FKED" 0402L 2575,700 r0 bottom value=4.99k
R18 "CRCW040210R0FKED" 0402L 2762,3882 r270 top value=10.0
R19 "CRCW04020000Z0ED" 0402L 3622,3490 r0 top value=0
R20 "CRCW0402100KFKED" 0402L 2987,3736 r90 top value=100k
R21 "CRCW04020000Z0ED" 0402L 3615,1230 r180 top value=0
R22 "CRCW04023R00JNED" 0402L 2762,3809 r90 top value=3.0
R23 "CRCW0402825RFKED" 0402L 4086,1436 r0 top value=825
R24 "CRCW04020000Z0ED" 0402L 2962,4048 r270 top value=0
R25 "CRCW0402909RFKED" 0402L 4469,3760 r90 top value=909
R26 "CRCW04020000Z0ED" 0402L 2816,3939 r180 top value=0
R27 "CRCW040211K3FKED" 0402L 3948,1616 r270 top value=11.3k
R28 "CRCW04020000Z0ED" 0402L 2922,4047 r90 top value=0
R29 "CRCW04022K49FKED" 0402L 3856,3728 r270 top value=2.49k
R30 "CRCW04022K49FKED" 0402L 3816,3728 r270 top value=2.49k
R31 "CRCW06030000Z0EA" 0603L 3715,4154 r270 top value=0
R32 "CRCW040211K3FKED" 0402L 3948,1457 r90 top value=11.3k
R33 "CRCW040247K5FKED" 0402L 3779,3728 r270 top value=47.5k
R34 "CRCW040210K0FKED" 0402L 4086,3932 r0 top value=10.0k
R35 "BLM15AX601SN1D" 0402L 3425,620 r180 top value="600 ohm"
R36 "BLM15AX601SN1D" 0402L 3615,620 r0 top value="600 ohm"
R37 "CRCW040210K0FKED" 0402L 3615,80 r270 top value=10.0k
R38 "CRCW040210K0FKED" 0402L 3650,80 r90 top value=10.0k
R39 "CRCW04020000Z0ED" 0402L 4067,239.14 r0 top value=0
R40 "CRCW0402100RFKED" 0402L 3852,239.14 r180 top value=100
R41 "CRCW04020000Z0ED" 0402L 4067,200.57 r0 top value=0
R42 "CRCW0402100RFKED" 0402L 3852,200.57 r180 top value=100
R43 "CRCW04020000Z0ED" 0402L 4067,393.43 r0 top value=0
R44 "CRCW0402100RFKED" 0402L 3852,393.43 r180 top value=100
R45 "CRCW04020000Z0ED" 0402L 4067,354.86 r0 top value=0
R46 "CRCW0402100RFKED" 0402L 3852,354.86 r180 top value=100
R47 "CRCW040247K5FKED" 0402L 4067,277.71 r180 top value=47.5k
R48 "CRCW040247K5FKED" 0402L 4067,162 r180 top value=47.5k
R49 "CRCW040247K5FKED" 0402L 4067,432 r180 top value=47.5k
R50 "CRCW040247K5FKED" 0402L 4067,316.29 r180 top value=47.5k
R51 "BLM15AX601SN1D" 0402L 3375,945 r270 top value="600 ohm"
R52 "BLM15AX601SN1D" 0402L 3615,1170 r0 top value="600 ohm"
R53 "CRCW040210K0FKED" 0402L 3555,665 r180 top value=10.0k
R54 "CRCW040210K0FKED" 0402L 3635,665 r180 top value=10.0k
R55 "CRCW04020000Z0ED" 0402L 4067,774.43 r0 top value=0
R56 "CRCW0402100RFKED" 0402L 3851,774.43 r180 top value=100
R57 "CRCW04020000Z0ED" 0402L 4067,734.71 r0 top value=0
R58 "CRCW0402100RFKED" 0402L 3851,734.71 r180 top value=100
R59 "CRCW04020000Z0ED" 0402L 4067,933.29 r0 top value=0
R60 "CRCW0402100RFKED" 0402L 3851,933.29 r180 top value=100
R61 "CRCW04020000Z0ED" 0402L 4067,893.57 r0 top value=0
R62 "CRCW0402100RFKED" 0402L 3851,893.57 r180 top value=100
R63 "CRCW040247K5FKED" 0402L 4067,814.14 r180 top value=47.5k
R64 "CRCW040247K5FKED" 0402L 4067,695 r180 top value=47.5k
R65 "CRCW040247K5FKED" 0402L 4067,973 r180 top value=47.5k
R66 "CRCW040247K5FKED" 0402L 4067,853.86 r180 top value=47.5k
R67 "CRCW040254R9FKED" 0402L 3170,1515 r90 top value=54.9
R68 "CRCW040254R9FKED" 0402L 3069,1496 r180 top value=54.9
R69 "CRCW040254R9FKED" 0402L 3123,1515 r90 top value=54.9
R70 "CRCW040254R9FKED" 0402L 2970,1330 r90 top value=54.9
R71 "CRCW040254R9FKED" 0402L 2950,1278 r180 top value=54.9
R72 "CRCW040254R9FKED" 0402L 2970,1220 r270 top value=54.9
R73 "CRCW04020000Z0ED" 0402L 4135,755 r90 top value=0
R74 "CRCW04020000Z0ED" 0402L 4194,835 r270 top value=0
R75 "CRCW04020000Z0ED" 0402L 4135,914 r90 top value=0
R76 "CRCW04020000Z0ED" 0402L 4135,555 r90 top value=0
R77 "CRCW04020000Z0ED" 0402L 4135,220 r90 top value=0
R78 "CRCW04020000Z0ED" 0402L 4194,296 r270 top value=0
R79 "CRCW04020000Z0ED" 0402L 4135,375 r90 top value=0
R80 "CRCW040254R9FKED" 0402L 2945,1110 r180 top value=54.9
R81 "CRCW040254R9FKED" 0402L 3025,1075 r180 top value=54.9
R82 "CRCW0402221RFKED" 0402L 4174,1436 r180 top value=221
R83 "CRCW04021K00FKED" 0402L 4153,1964 r90 top value=1.00k
R84 "CRCW04021K00FKED" 0402L 4153,1875 r270 top value=1.00k
R85 "CRCW04021K00FKED" 0402L 4039,1814 r0 top value=1.00k
R86 "ERJ-3RQFR51V" 0603 1177,3758 r0 top value=0.51
S1 "SKRKAEE010" SW_SKRKAEE010 3896,4041 r180 top
S2 "SKRKAEE010" SW_SKRKAEE010 5164,3711 r0 top
S3 "SKRKAEE010" SW_SKRKAEE010 5164,3489 r0 top
T1 "CB35-36-CY" CB35-36-CY 350,4130 r0 top
T2 "CB35-36-CY" CB35-36-CY 350,3500 r0 top
TP3 "5011" Keystone5011 3352,4359 r0 top
TP5 "5010" Keystone5010 3557,4130 r270 top
TP6 "TESTPOINT" PAD_1MM_SQUARE 3801,3817 r0 top
TP7 "TESTPOINT" PAD_1MM_SQUARE 3867,3817 r270 top
TP8 "TESTPOINT" PAD_1MM_SQUARE 4105,3520 r270 top
TP9 "TESTPOINT" PAD_1MM_SQUARE 4040,3522 r270 top
TP12 "TESTPOINT" PAD_1MM_SQUARE 3331,472 r180 top locked
TP14 "TESTPOINT" PAD_1MM_SQUARE 3245,1445 r90 top
TP15 "TESTPOINT" PAD_1MM_SQUARE 3330,690 r90 top
U1 "TAS6424QDKQRQ1" DKQ0056A 2274,2634 r180 bottom
U2 "TAS6424QDKQRQ1" DKQ0056A 2274,950 r180 bottom
U3 "LM53635LQRNLRQ1" RNL0022A_NV 3019,3884 r90 top
U4 "TLV2462AQDRQ1" D0008A_N 4085,1636 r270 top
U5 "LP5907QMFX-3.3Q1" DBV0005A_N 3792,1267 r180 top
U6 "LP5912Q3.3DRVRQ1" DRV0006A 3642,3630 r90 top
U7 "MSP430G2332QPW2REP" PW0020A_N 4100,3735 r90 top
U8 "PCM1865QDBTRQ1" DBT0030A_N 3573,292 r270 top locked
U9 "PCM1865QDBTRQ1" DBT0030A_N 3573,840 r270 top locked
U10 "SN74LVC125AQPWRQ1" PW0014A_N 3123,1270 r270 top
U11 "LM74610QDGKRQ1" DGK0008A_L 2102,3950 r270 top
U12 "LM74700QDDCRQ1" DDC0006A_N 2102,3950 r0 bottom
Y1 "ABM10AIG-24.576MHZ-J4Z-T3" Abracon_ABM10AIG 3511,1218 r0 top
ZZ1 "This Assembly Note is for PCB labels only" AssemblyNoteLabel 686,6574 r0 top

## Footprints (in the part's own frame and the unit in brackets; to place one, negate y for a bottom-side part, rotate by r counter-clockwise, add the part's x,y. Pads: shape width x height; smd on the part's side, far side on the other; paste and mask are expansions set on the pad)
0402L [mm] "0402 from SM-752 data"
  rect 0.6x0.5 smd: 1(-0.5,0) 2(0.5,0)
  body extent -0.55,-0.3 0.55,0.3, height 0.6
0603 [mm] "0603 from SM-752 data"
  rect 1x0.95 smd: 1(-0.8,0) 2(0.8,0)
  silkscreen extent -1.52,-0.69 1.52,0.69, body extent -0.87,-0.47 0.87,0.47, height 1
0603L [mm] "0603 from SM-752 data"
  rect 0.8x0.85 smd: 1(-0.7,0) 2(0.7,0)
  silkscreen extent -0.07,-0.33 0.07,0.33, body extent -0.87,-0.47 0.87,0.47, height 1
0805L#1 [mm] "0805 from SM-752 data"
  rect 1.1x1.4 smd: 1(-0.75,0) 2(0.75,0)
  body extent -1.1,-0.72 1.1,0.72, height 1.45
0805L#2 [mm] "0805 from SM-752 data"
  rect 1.4x1.1 smd: 1(0,0.75) 2(0,-0.75)
  body extent -0.72,-1.1 0.72,1.1, height 1.45
1206_180 [mm] "1206_180"
  rect 1.1x1.6 smd: 1(-1.7,0) 2(1.7,0)
  silkscreen extent -0.9,-1 0.9,1, body extent -1.75,-0.95 1.75,0.95, height 1.8
1210_270 [mm] "1210"
  rect 1.3x2.7 smd: 1(-1.45,0) 2(1.45,0)
  silkscreen extent -2.32,-1.57 2.32,1.57, body extent -1.7,-1.35 1.7,1.35, height 2.7
1210_280 [mm] "SMD, 2-Leads, Body 3.6x2.8mm, Height 2.8mm"
  rect 1.1x2.2 smd: 1(-1.65,0) 2(1.65,0)
  silkscreen extent -0.84,-1.4 0.84,1.4, body extent -1.8,-1.4 1.8,1.4, height 2.8
Abracon_ABM10AIG [mm] "SMD, 4-Leads, Body 2.5x2mm"
  rect 0.8x0.95 smd: 1(-0.65,0.825) 2(-0.65,-0.825) 3(0.65,-0.825) 4(0.65,0.825)
  silkscreen extent -1.49,0.76 -1.36,0.89, body extent -1.05,-1.3 1.05,1.3, height 0.6
AssemblyNoteLabel [mil] "Assembly Note for PCB Labels"
CB35-36-CY [mil] "Terminal 50A Lug"
  rect 550x380 hole 188 copper offset -45,0 paste-190: 1(0,0)
  body extent -960,-189 230,191, height 614
CONN_851-43-006-20-001000 [mil] "Mill-Max"
  rect 36x70 hole 26: 1(125,0)
  oval 36x70 hole 26: 2(75,0) 3(25,0) 4(-25,0) 5(-75,0) 6(-125,0)
  silkscreen extent -160,-210 160,-50, body extent -157,-210 157,8, height 87
Cyntec_VAMV06077E [mm] "SMD, 4-Leads, Body 7.6x6.9mm"
  rect 3.2x2 smd: 1(-3.375,1.625) 2(-3.375,-1.625) 3(3.375,-1.625) 4(3.375,1.625)
  silkscreen extent -3.9,-3.55 3.9,3.8, body extent -3.9,-3.55 3.9,3.55, height 7.5
D0008A_N [mm] "SOIC, 8-Leads, Body 4.9x3.9mm, Pitch 1.27mm, IPC Medium Density"
  oval 1.45x0.6 smd: 1(-2.725,1.905) 2(-2.725,0.635) 3(-2.725,-0.635) 4(-2.725,-1.905) 5(2.725,-1.905) 6(2.725,-0.635) 7(2.725,0.635) 8(2.725,1.905)
  silkscreen extent -3.3,-2.5 0.9,2.5, body extent -3,-2.45 3,2.45, height 1.63
DBT0030A_N [mm] "TSSOP, 30-Leads, Body 7.8x4.4mm, Pitch 0.5mm, IPC Medium Density"
  oval 1.4x0.3 smd: 1(-2.95,3.5) 2(-2.95,3) 3(-2.95,2.5) 4(-2.95,2) 5(-2.95,1.5) 6(-2.95,1) 7(-2.95,0.5) 8(-2.95,0) 9(-2.95,-0.5) 10(-2.95,-1) 11(-2.95,-1.5) 12(-2.95,-2) 13(-2.95,-2.5) 14(-2.95,-3) 15(-2.95,-3.5) 16(2.95,-3.5) 17(2.95,-3) 18(2.95,-2.5) 19(2.95,-2) 20(2.95,-1.5) 21(2.95,-1) 22(2.95,-0.5) 23(2.95,0) 24(2.95,0.5) 25(2.95,1) 26(2.95,1.5) 27(2.95,2) 28(2.95,2.5) 29(2.95,3) 30(2.95,3.5)
  silkscreen extent -3.42,-3.95 1.5,3.95, body extent -3.21,-3.9 3.21,3.9, height 1.2
DBV0005A_N [mm] "SOT23, 5-Leads, Body 2.9x1.6mm, Pitch 0.95mm, Lead Span 2.8mm, IPC Medium Density"
  rrect17% 1x0.6 smd: 1(-1.375,0.95) 2(-1.375,0) 3(-1.375,-0.95) 4(1.375,-0.95) 5(1.375,0.95)
  silkscreen extent -1.63,-1.55 0.38,1.55, body extent -1.42,-1.46 1.42,1.46, height 1.09
DDC0006A_N [mm]
  rrect17% 1x0.6 smd: 1(-1.375,0.95) 2(-1.375,0) 3(-1.375,-0.95) 4(1.375,-0.95) 5(1.375,0) 6(1.375,0.95)
  silkscreen extent -1.75,-1.52 0.7,1.53, body extent -1.43,-1.48 1.43,1.49, height 0.92
DGK0008A_L [mm] "TSOP, 8-Leads, Body 3x3mm, Pitch 0.65mm, IPC High Density"
  oval 1.15x0.45 smd: 1(-2.125,0.975) 2(-2.125,0.325) 3(-2.125,-0.325) 4(-2.125,-0.975) 5(2.125,-0.975) 6(2.125,-0.325) 7(2.125,0.325) 8(2.125,0.975)
  silkscreen extent -2.58,-1.55 0.95,1.55, body extent -2.45,-1.5 2.45,1.5, height 0.96
DKQ0056A [mm] "SOP, 56-Leads, Body 18.415x7.49mm, Pitch 0.635mm"
  rrect25% 1.9x0.4 smd: 1(-4.75,8.572) 2(-4.75,7.938) 3(-4.75,7.302) 4(-4.75,6.667) 5(-4.75,6.033) 6(-4.75,5.398) 7(-4.75,4.763) 8(-4.75,4.128) 9(-4.75,3.493) 10(-4.75,2.858) 11(-4.75,2.223) 12(-4.75,1.588) 13(-4.75,0.953) 14(-4.75,0.318) 15(-4.75,-0.317) 16(-4.75,-0.952) 17(-4.75,-1.587) 18(-4.75,-2.222) 19(-4.75,-2.857) 20(-4.75,-3.492) 21(-4.75,-4.127) 22(-4.75,-4.762) 23(-4.75,-5.397) 24(-4.75,-6.032) 25(-4.75,-6.667) 26(-4.75,-7.302) 27(-4.75,-7.938) 28(-4.75,-8.572) 29(4.75,-8.572) 30(4.75,-7.938) 31(4.75,-7.302) 32(4.75,-6.667) 33(4.75,-6.033) 34(4.75,-5.398) 35(4.75,-4.763) 36(4.75,-4.128) 37(4.75,-3.493) 38(4.75,-2.858) 39(4.75,-2.223) 40(4.75,-1.588) 41(4.75,-0.953) 42(4.75,-0.318) 43(4.75,0.317) 44(4.75,0.952) 45(4.75,1.587) 46(4.75,2.222) 47(4.75,2.857) 48(4.75,3.492) 49(4.75,4.127) 50(4.75,4.762) 51(4.75,5.397) 52(4.75,6.032) 53(4.75,6.667) 54(4.75,7.302) 55(4.75,7.938) 56(4.75,8.572)
  silkscreen extent -5.55,-9.2 3.74,9.2, body extent -5.18,-9.21 5.17,9.21, height 2.32
DRV0006A [mm] "SON, 6-Leads, Body 2x2mm, Pitch 0.65mm, Thermal Pad 1.6x1mm, TI Recommended"
  rrect33% 0.45x0.3 smd: 1(-0.975,0.65) 2(-0.975,0) 3(-0.975,-0.65) 4(0.975,-0.65) 5(0.975,0) 6(0.975,0.65)
  rrect14% 1x0.7 on Top Paste: 7(0,0.45) 7(0,-0.45)
  rrect10% 1x1.6 smd paste-0.5: 7(0,0)
  silkscreen extent -1.05,-1.2 1.05,1.2, body extent -1.05,-1.05 1.05,1.05, height 0.81
FCC_disclaimer [mil]
Fiducial10-30 [mm]
  round 1 smd mask+1: 1(0,0)
  Top Layer keep-out circle w1.678: c0,0 r0.75
IEC_HotSurface_Medium [mil]
  silkscreen extent -217,-188 217,188
IHLP-5050CE [mm] "Vishay Dale recommended land pattern.  Document 34105 rev 10-Aug-06"
  rect 2.85x3.3 smd: 1(-5.475,0) 2(5.475,0)
  silkscreen extent -6.6,-6.5 6.6,6.5, body extent -6.79,-6.45 6.79,6.45, height 3.5
Keystone5010 [mil] "Keystone Multipurpose loops"
  round 87 hole 63: 1(0,0)
  silkscreen extent -70,-70 70,70, body extent -63,-63 63,62, height 319
Keystone5011 [mil] "Keystone Multipurpose loops"
  round 87 hole 63: 1(0,0)
  silkscreen extent -70,-70 70,70, body extent -63,-63 63,62, height 319
Molex_0022284023 [mm] "Header, 2.54mm, 2x1, TH"
  rect 1.55x1.55 hole 1.02: 1(-1.27,0)
  round 1.55 hole 1.02: 2(1.27,0)
  silkscreen extent -2.54,-1.24 2.54,1.5, body extent -2.54,-1.24 2.54,1.24, height 8.4
MTGP_4-40_PanHead [mm] "4-40 Mounting Hole, Plated, for Pan Head"
  round 6.4 hole 3.5: 1(0,0)
Net-Tie_50milWide_30milLong [mil] "50mil net tie, no solder mask opening, no solder paste"
  rect 30x50 smd paste-20 mask-20: 1(-15,0) 2(15,0)
On-Shore_OSTTE080161 [mm] "Term Blk 8x1"
  rect 1.7x1.7 hole 1.2: 1(-12.25,0)
  round 1.7 hole 1.2: 2(-8.75,0) 3(-5.25,0) 4(-1.75,0) 5(1.75,0) 6(5.25,0) 7(8.75,0) 8(12.25,0)
  silkscreen extent -14.97,-3.4 14,3.6, body extent -14,-3.4 14,3.6, height 8.4
PAD_1MM_SQUARE [mm]
  rect 1x1 smd: 1(0,0)
Pb-Free_Overlay_Medium [mil]
  silkscreen extent -95,-95 95,95
Phoenix_1714955 [mm] "Terminal Block, 2x1, 6.35mm, TH"
  rect 1.8x1.8 hole 1.3: 1(-3.175,0)
  round 1.8 hole 1.3: 2(3.175,0)
  silkscreen extent -6.7,-7.9 6.35,4.6, body extent -6.92,-7.9 6.35,4.6, height 21.5
PW0014A_N [mm] "TSOP, 14-Leads, Body 5x4.4mm, Pitch 0.65mm, IPC Medium Density"
  oval 1.4x0.45 smd: 1(-2.95,1.95) 2(-2.95,1.3) 3(-2.95,0.65) 4(-2.95,0) 5(-2.95,-0.65) 6(-2.95,-1.3) 7(-2.95,-1.95) 8(2.95,-1.95) 9(2.95,-1.3) 10(2.95,-0.65) 11(2.95,0) 12(2.95,0.65) 13(2.95,1.3) 14(2.95,1.95)
  silkscreen extent -3.4,-2.55 1.85,2.55, body extent -3.21,-2.5 3.21,2.5, height 1
PW0020A_N [mm] "TSOP, 20-Leads, Body 6.5x4.4mm, Pitch 0.65mm, IPC Medium Density"
  oval 1.4x0.45 smd: 1(-2.95,2.925) 2(-2.95,2.275) 3(-2.95,1.625) 4(-2.95,0.975) 5(-2.95,0.325) 6(-2.95,-0.325) 7(-2.95,-0.975) 8(-2.95,-1.625) 9(-2.95,-2.275) 10(-2.95,-2.925) 11(2.95,-2.925) 12(2.95,-2.275) 13(2.95,-1.625) 14(2.95,-0.975) 15(2.95,-0.325) 16(2.95,0.325) 17(2.95,0.975) 18(2.95,1.625) 19(2.95,2.275) 20(2.95,2.925)
  silkscreen extent -3.5,-3.3 1.85,3.4, body extent -3.21,-3.25 3.21,3.25, height 1
RNL0022A_NV [mm] "VQFN, 22 pin, 0.5 mm pitch"
  rrect25% 0.7x0.5 smd paste-0.05 mask-0.05: 1(-1.9,2) 17(1.9,2)
  rrect40% 0.7x0.35 smd paste-0.05 mask-0.05: 2(-1.9,1.425) 3(-1.9,0.575) 15(1.9,0.575) 16(1.9,1.425)
  rrect40% 1.1x0.5 smd paste-0.25 mask-0.05: 4(-1.7,-0.25) 14(1.7,-0.25)
  rrect25% 0.4x0.4 on Top Paste: 4A(-2,-0.25) 4B(-1.4,-0.25) 14A(1.4,-0.25) 14B(2,-0.25)
  rrect57% 0.7x0.35 smd paste-0.05 mask-0.05: 5(-1.9,-1.175) 6(-1.9,-1.675) 7(-1.9,-2.175) 11(1.9,-2.175) 12(1.9,-1.675) 13(1.9,-1.175)
  rrect40% 0.5x1.74 smd paste-0.25 mask-0.05: 8(-1,-1.875) 10(1,-1.875)
  rrect25% 0.4x0.66 on Top Paste: 8A(-1,-1.445) 8B(-1,-2.305) 10A(1,-1.445) 10B(1,-2.305)
  rrect40% 0.5x3.25 smd paste-0.25 mask-0.05: 9(0,-1.125)
  rrect25% 0.4x0.63 on Top Paste: 9A(0,0.12) 9B(0,-0.71) 9C(0,-1.54) 9D(0,-2.37)
  rrect40% 0.35x0.85 smd paste-0.05 mask-0.05: 18(1,2.325) 19(0.5,2.325) 20(0,2.325) 21(-0.5,2.325) 22(-1,2.325)
  silkscreen extent -2.15,-2.65 2.15,2.65, body extent -2.05,-2.55 2.05,2.55, height 0.91
SM_RADIAL_J16 [mm] "16 x 16.5mm:  Panasonic J16"
  rect 6.5x2.5 smd: 1(-6.25,0) 2(6.25,0)
  silkscreen extent -8.6,-8.6 8.6,8.6, body extent -8.6,-8.6 8.6,8.6, height 17
SMB [mil] "Molded Diode, 2-Leads, Body 5.4x3.6mm, IPC Medium Density, based on OnSemi component dimensions"
  rect 85x107.99 smd: 1(-87.01,0) 2(87.01,0)
  silkscreen extent -155,-82 125,82, body extent -106,-71 106,71, height 91
SW_SKRKAEE010 [mm] "Alps recommended land pattern"
  rect 0.8x2 smd: 1(-2.1,0) 2(2.1,0)
  silkscreen extent -1.9,-1.44 1.92,1.44, body extent -2.4,-1.45 2.4,1.45, height 1.96
Switchcraft_35RASM [mil] "Switchcraft"
  rect 83x92 smd: 1(-159.5,142.5) 2(159.5,67.5)
  rect 83x111 smd: 3(-159.5,-224.5)
  rect 83x84 smd: 4(159.5,173.5)
  rect 111x107 smd: 5(29,-390.5)
  rect 0x0 hole 63 unplated: MH1(0,98.5) MH2(0,-177.5)
  silkscreen extent -161,-340 121,340, body extent -120,-339 120,340, height 202
TDSON-8_FL [mm] "SMD, 8-Leads, Body 6x5mm, Pitch 1.27mm"
  rect 0.35x0.4 smd mask+0: 1(-3.095,1.905) 2(-3.095,0.635) 3(-3.095,-0.635)
  rect 1.1x0.5 smd paste-0.5: 4(-2.775,-1.905)
  rect 0.75x0.5 smd mask+0: 5(2.895,-1.905) 6(2.895,-0.635) 7(2.895,0.635) 8(2.895,1.905)
  rect 1x1 smd paste-1: 9(0,0)
  Top Layer region: 2.525,-1.605 2.525,-0.935 3.325,-0.935 3.325,-0.335 2.525,-0.335 2.525,0.335 3.325,0.335 3.325,0.935 2.525,0.935 2.525,1.605 3.325,1.605 3.325,2.205 -1.225,2.205 -1.225,-2.205 3.325,-2.205 3.325,-1.605
  Top Layer region: -3.325,-0.885 -3.325,-0.385 -2.825,-0.385 -2.825,0.385 -3.325,0.385 -3.325,0.885 -2.825,0.885 -2.825,1.655 -3.325,1.655 -3.325,2.155 -2.825,2.155 -2.825,2.315 -2.225,2.315 -2.225,-0.885
  silkscreen extent -3.1,-2.6 3.1,2.6, body extent -3,-2.5 3,2.5, height 1.1
WL-SMCW_GREEN [mm] "WURTH"
  rect 0.8x0.8 smd: 1(-0.8,0) 2(0.8,0)
  silkscreen extent -1.9,-0.8 1.2,0.8, body extent -0.85,-0.45 0.85,0.45, height 0.8
WL-SMCW_RED [mm] "WURTH"
  rect 0.8x0.8 smd: 1(-0.8,0) 2(0.8,0)
  silkscreen extent -1.9,-0.8 1.2,0.8, body extent -0.85,-0.45 0.85,0.45, height 0.8
WL-SMCW_YELLOW [mm] "WURTH"
  rect 0.8x0.8 smd: 1(-0.8,0) 2(0.8,0)
  silkscreen extent -1.9,-0.8 1.2,0.8, body extent -0.85,-0.45 0.85,0.45, height 0.8
XAL6030 [mil] "Coilcraft recommended land pattern Document 887-4 Revised 11/20/12"
  rect 56x224 smd: 1(-79.5,0) 2(79.5,0)
  silkscreen extent -129,-133 129,133, body extent -129,-133 129,133, height 122

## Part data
C1 C41: "CAP, AL, 1000 µF, 50 V, +/- 20%, 0.073 ohm, SMD", Cap_Case=J16, Manufacturer=Panasonic, Supplier Part Number 1=PCE3477CT-ND, Tolerance_%=20, Value1="0.073 ohm", Value2=50V, ValueDisplayed=1000µF
C2 C4 C6 C8 C44 C46 C48 C50 C85 C86 C88 C89: "CAP, CERM, 10 µF, 50 V, +/- 10%, X7R, 1210", Cap_Case=1210, Manufacturer=MuRata, Supplier Part Number 1=490-6544-1-ND, TempCo=X7R, Tolerance_%=10, Value1=Unknown, Value2=50V, ValueDisplayed=10µF
C3 C5 C7 C9 C45 C47 C49 C51 C60 C81 C83 C87 C90 C95 C99 C101 C105 C107 C108 C109 C110 C118 C121 C125 C127 C128 C129 C130 C139 C146 C147 C150 C151: "CAP, CERM, 0.1 µF, 50 V, +/- 10%, X7R, 0402", Cap_Case=0402, Manufacturer=TDK, Supplier Part Number 1=445-5932-1-ND, TempCo=X7R, Tolerance_%=10, Value1="0.039064 ohm", Value2=50V, ValueDisplayed=0.1µF
C10 C12 C17 C25 C31 C35 C37 C39 C42 C52 C57 C64 C71 C75 C77 C79 C106 C126: "CAP, CERM, 1 µF, 50 V, +/- 10%, X7R, 0805", Cap_Case=0805, Manufacturer=MuRata, Supplier Part Number 1=490-4736-1-ND, TempCo=X7R, Tolerance_%=10, Value1=Unknown, Value2=50V, ValueDisplayed=1µF
C11 C13 C18 C26 C32 C36 C38 C40 C43 C53 C58 C65 C72 C76 C78 C80 C148 C149: "CAP, CERM, 0.01 µF, 50 V, +/- 10%, C0G/NP0, 0402", Cap_Case=0402, Manufacturer=MuRata, Supplier Part Number 1=490-4762-1-ND, TempCo=C0G/NP0, Tolerance_%=10, Value1=Unknown, Value2=50V, ValueDisplayed=0.01µF
C14 C16 C19 C22 C27 C28 C33 C34 C54 C56 C59 C62 C67 C68 C73 C74 C152 C153: "CAP, CERM, 2.2 µF, 50 V, +/- 10%, X7R, 0805", Cap_Case=0805, Manufacturer=TDK, Supplier Part Number 1=445-5968-1-ND, TempCo=X7R, Tolerance_%=10, Value1="0.00366 ohm", Value2=50V, ValueDisplayed=2.2µF
C15 C20 C21 C23 C24 C29 C30 C55 C61 C63 C66 C69 C70 C119 C142 C143 C144 C145: "CAP, CERM, 1 µF, 25 V, +/- 10%, X7R, 0603", Cap_Case=0603, Manufacturer=TDK, Supplier Part Number 1=445-5956-1-ND, TempCo=X7R, Tolerance_%=10, Value1=Unknown, Value2=25V, ValueDisplayed=1µF
C82 C140: "CAP, CERM, 4.7 µF, 50 V, +/- 10%, X7R, 1206", Cap_Case=2220, Manufacturer=MuRata, Supplier Part Number 1=81-GRM31CR71H475KA2L, TempCo=X7R, Tolerance_%=10, Value1=Unknown, Value2=50V, ValueDisplayed=4.7µF
C84: "CAP, CERM, 0.47 µF, 25 V, +/- 10%, X7R, 0603", Cap_Case=0603, Manufacturer=MuRata, Supplier Part Number 1=490-3291-1-ND, TempCo=X7R, Tolerance_%=10, Value1=Unknown, Value2=25V, ValueDisplayed=0.47µF
C91 C92 C93: "CAP, CERM, 22 µF, 16 V, +/- 20%, X7R, AEC-Q200 Grade 1, 1210", Cap_Case=1210_280, Manufacturer=TDK, Supplier Part Number 1=445-5723-1-ND, TempCo=X7R, Tolerance_%=20, Value1="0.002582 ohm", Value2=16V, ValueDisplayed=22µF
C94: "CAP, CERM, 4.7 µF, 10 V, +/- 10%, X7R, 0805", Cap_Case=0805, Manufacturer=MuRata, Supplier Part Number 1=GRM21BR71A475KA73L-ND, TempCo=X7R, Tolerance_%=10, Value1=Unknown, Value2=10V, ValueDisplayed=4.7µF
C96: "CAP, CERM, 2200 pF, 50 V, +/- 10%, X7R, 0402", Cap_Case=0402, Manufacturer=MuRata, Supplier Part Number 1=490-1305-1-ND, TempCo=X7R, Tolerance_%=10, Value1=Unknown, Value2=50V, ValueDisplayed=2200pF
C97 C100 C102 C103 C104 C112 C117 C120 C122 C123 C124 C132: "CAP, CERM, 10 µF, 10 V, +/- 10%, X7R, 0805", Cap_Case=0805, Manufacturer=MuRata, Supplier Part Number 1=490-3905-1-ND, TempCo=X7R, Tolerance_%=10, Value1="0.003 ohm", Value2=10V, ValueDisplayed=10µF
C98: "CAP, CERM, 1000 pF, 50 V, +/- 10%, C0G/NP0, 0603", Cap_Case=0603, Manufacturer=AVX, Supplier Part Number 1=478-3718-1-ND, TempCo=C0G/NP0, Tolerance_%=10, Value1="0.048 ohm", Value2=50V, ValueDisplayed=1000pF
C111 C131: "CAP, CERM, 2.2 µF, 6.3 V, +/- 10%, X7R, AEC-Q200 Grade 1, 0603", Cap_Case=0603, Manufacturer=MuRata, Supplier Part Number 1=490-5316-1-ND, TempCo=X7R, Tolerance_%=10, Value1=Unknown, Value2=6.3V, ValueDisplayed=2.2µF
C113 C114 C115 C116 C133 C134 C135 C136: "CAP, CERM, 0.01 µF, 16 V, +/- 10%, X7R, 0402", Cap_Case=0402, Manufacturer="Wurth Elektronik", Supplier Part Number 1=710-885012205031, TempCo=X7R, Tolerance_%=10, Value1=Unknown, Value2=16V, ValueDisplayed=0.01µF
C137 C138: "CAP, CERM, 20 pF, 50 V, +/- 5%, C0G/NP0, 0402", Cap_Case=0402, Manufacturer=MuRata, Supplier Part Number 1=81-GRM1555C1H200JA1D, TempCo=C0G/NP0, Tolerance_%=5, Value1=Unknown, Value2=50V, ValueDisplayed=20pF
C141: "CAP, CERM, 0.022 µF, 50 V,+/- 10%, X7R, 0402", Cap_Case=0402, Manufacturer=MuRata, Supplier Part Number 1=490-3884-1-ND, TempCo=X7R, Tolerance_%=10, Value2=50V, ValueDisplayed=0.022µF
D1: "LED, Super Red, SMD", Color="super red", Manufacturer="Wurth Elektronik", Supplier Part Number 1=732-4979-1-ND, Value1=W, Value2=1.9V
D2: "LED, Yellow, SMD", Color=yellow, Manufacturer="Wurth Elektronik", Supplier Part Number 1=732-4981-1-ND, Value1=W, Value2=2V
D5: "Diode, TVS, Uni, 17 V, 600 W, SMB", Manufacturer="Diodes Inc.", Power_W=5, Supplier Part Number 1=SMBJ17A-FDICT-ND, Value1=5W
D6: "Diode, TVS, Uni, 14 V, 600 W, SMB", Manufacturer="Diodes Inc.", Power_W=5, Supplier Part Number 1=SMBJ14A-FDICT-ND, Value1=5W
D7: "LED, Green, SMD", Color=green, Manufacturer="Wurth Elektronik", Supplier Part Number 1=732-4980-1-ND, Value1=W, Value2=2V
FID1 FID2 FID3: "Fiducial mark.  There is nothing to buy or mount.", Manufacturer=N/A
J1 J2: "Terminal Block, 8x1, 3.5mm, TH", Manufacturer="On-Shore Technology", Supplier Part Number 1=ED2641-ND
J3 J4: "Header, 2.54mm, 2x1, Tin, TH", Color=Black, Current_A=4, Manufacturer=Molex, Supplier Part Number 1=WM50016-02-ND, Voltage_V=250
J5: "Receptacle, 50mil, 6x1, Gold, R/A, TH", Manufacturer=Mill-Max
J6 J7 J8 J9: "Audio Jack, 3.5mm, Stereo, R/A, SMT", Manufacturer=Switchcraft, Supplier Part Number 1=SC1488-1-ND
J10: "Terminal Block, 2x1, 6.35mm, Green, TH", Color=Green, Manufacturer="Phoenix Contact", Supplier Part Number 1=277-1269-ND
L1 L2 L3 L4 L5 L6 L7 L8: "Coupled inductor, 3.3 µH, 11.1 A, 0.0192 ohm, SMD", Manufacturer=Cyntec, ValueDisplayed=3.3µH
L9: "Inductor, Shielded, Composite, 2.2 µH, 12.7 A, 0.012 ohm, SMD", Manufacturer=Coilcraft, Value1="0.012 ohm", Value2=12.7A, ValueDisplayed=2.2µH
L18: "Inductor, Shielded Drum Core, Powdered Iron, 470 nH, 32 A, 0.0016 ohm, SMD", Manufacturer=Vishay-Dale, Supplier Part Number 1=541-1014-1-ND, Value1="0.0016 ohm", Value2=32A, ValueDisplayed=470nH
LOGO1 LOGO4 LOGO6: library part IEC_HotSurface, "IEC 61010-1 Hot Surface Warning"
Logo2: library part Pb-Free
Logo3: library part FCC_disclaimer, "FCC_disclaimer"
MH1 MH2 MH3: library part "Mounting Hole (Imperial) with Pads", "PCB Mounting Hole", Manufacturer=Any, PartNumber=N/A
NTG: "Single point connection between nets."
Q1: library part CMP-0000679-1, "MOSFET, N-CH, 40 V, 100 A, 8-PowerTDFN", Alternate Manufacturer=None, Manufacturer="Infineon Technologies", Supplier Part Number 1=50Y1798, Value1=0, Value2="29 nC"
R1 R12: "RES, 0, 5%, 0.125 W, 0805", Manufacturer=Vishay-Dale, Power_W=0.125, Supplier Part Number 1=541-0.0ACT-ND, TempCo="200 ppm/C", Tolerance_%=5, Value1=5%, Value2=0.125W, Value_Code=0000, ValueDisplayed=0
R2: "RES, 71.5 k, 1%, 0.063 W, 0402", Manufacturer=Vishay-Dale, Power_W=0.063, Supplier Part Number 1=541-71.5KLCT-ND, TempCo="100 ppm/C", Tolerance_%=1, Value1=1%, Value2=0.063W, Value_Code=71k5, ValueDisplayed=71.5k
R3 R8 R15 R17: "RES, 4.99 k, 1%, 0.063 W, 0402", Manufacturer=Vishay-Dale, Power_W=0.063, Supplier Part Number 1=541-4.99KLCT-ND, TempCo="100 ppm/C", Tolerance_%=1, Value1=1%, Value2=0.063W, Value_Code=4k99, ValueDisplayed=4.99k
R4 R7 R14 R16 R20: "RES, 100 k, 1%, 0.063 W, 0402", Manufacturer=Vishay-Dale, Power_W=0.063, Supplier Part Number 1=541-100KLCT-ND, TempCo="100 ppm/C", Tolerance_%=1, Value1=1%, Value2=0.063W, Value_Code=100k
R5 R6 R34 R37 R38 R53 R54: "RES, 10.0 k, 1%, 0.063 W, 0402", Manufacturer=Vishay-Dale, Power_W=0.063, Supplier Part Number 1=541-10.0KLCT-ND, TempCo="100 ppm/C", Tolerance_%=1, Value1=1%, Value2=0.063W, Value_Code=10k0, ValueDisplayed=10.0k
R9 R22: "RES, 3.0, 5%, 0.063 W, 0402", Manufacturer=Vishay-Dale, Power_W=0.063, Supplier Part Number 1=541-3.0JCT-ND, TempCo="200 ppm/C", Tolerance_%=5, Value1=5%, Value2=0.063W, Value_Code=3R00, ValueDisplayed=3.0
R10 R11 R83 R84 R85: "RES, 1.00 k, 1%, 0.063 W, 0402", Manufacturer=Vishay-Dale, Power_W=0.063, Supplier Part Number 1=541-1.00KLCT-ND, TempCo="100 ppm/C", Tolerance_%=1, Value1=1%, Value2=0.063W, Value_Code=1k00, ValueDisplayed=1.00k
R13: "RES, 8.06, 1%, 0.063 W, 0402", Manufacturer=Vishay-Dale, Power_W=0.063, Supplier Part Number 1=541-8.06LLCT-ND, TempCo="100 ppm/C", Tolerance_%=1, Value1=1%, Value2=0.063W, Value_Code=8R06, ValueDisplayed=8.06
R18: "RES, 10.0, 1%, 0.063 W, 0402", Manufacturer=Vishay-Dale, Power_W=0.063, Supplier Part Number 1=541-10.0LCT-ND, TempCo="100 ppm/C", Tolerance_%=1, Value1=1%, Value2=0.063W, Value_Code=10R0, ValueDisplayed=10.0
R19 R21 R24 R26 R28 R39 R41 R43 R45 R55 R57 R59 R61 R73 R74 R75 R76 R77 R78 R79: "RES, 0, 5%, 0.063 W, 0402", Manufacturer=Vishay-Dale, Power_W=0.063, Supplier Part Number 1=541-0.0JCT-ND, TempCo="200 ppm/C", Tolerance_%=5, Value1=5%, Value2=0.063W, Value_Code=0000, ValueDisplayed=0
R23: "RES, 825, 1%, 0.063 W, 0402", Manufacturer=Vishay-Dale, Power_W=0.063, Supplier Part Number 1=541-825LCT-ND, TempCo="100 ppm/C", Tolerance_%=1, Value1=1%, Value2=0.063W, Value_Code=825R, ValueDisplayed=825
R25: "RES, 909, 1%, 0.063 W, 0402", Manufacturer=Vishay-Dale, Power_W=0.063, Supplier Part Number 1=541-909LCT-ND, TempCo="100 ppm/C", Tolerance_%=1, Value1=1%, Value2=0.063W, Value_Code=909R, ValueDisplayed=909
R27 R32: "RES, 11.3 k, 1%, 0.063 W, 0402", Manufacturer=Vishay-Dale, Power_W=0.063, Supplier Part Number 1=541-11.3KLCT-ND, TempCo="100 ppm/C", Tolerance_%=1, Value1=1%, Value2=0.063W, Value_Code=11k3, ValueDisplayed=11.3k
R29 R30: "RES, 2.49 k, 1%, 0.063 W, 0402", Manufacturer=Vishay-Dale, Power_W=0.063, Supplier Part Number 1=541-2.49KLCT-ND, TempCo="100 ppm/C", Tolerance_%=1, Value1=1%, Value2=0.063W, Value_Code=2k49, ValueDisplayed=2.49k
R31: "RES, 0, 5%, 0.1 W, 0603", Manufacturer=Vishay-Dale, Power_W=0.1, Supplier Part Number 1=541-0.0GCT-ND, TempCo="200 ppm/C", Tolerance_%=5, Value1=5%, Value2=0.1W, Value_Code=0000, ValueDisplayed=0
R33 R47 R48 R49 R50 R63 R64 R65 R66: "RES, 47.5 k, 1%, 0.063 W, 0402", Manufacturer=Vishay-Dale, Power_W=0.063, Supplier Part Number 1=541-47.5KLCT-ND, TempCo="100 ppm/C", Tolerance_%=1, Value1=1%, Value2=0.063W, Value_Code=47k5, ValueDisplayed=47.5k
